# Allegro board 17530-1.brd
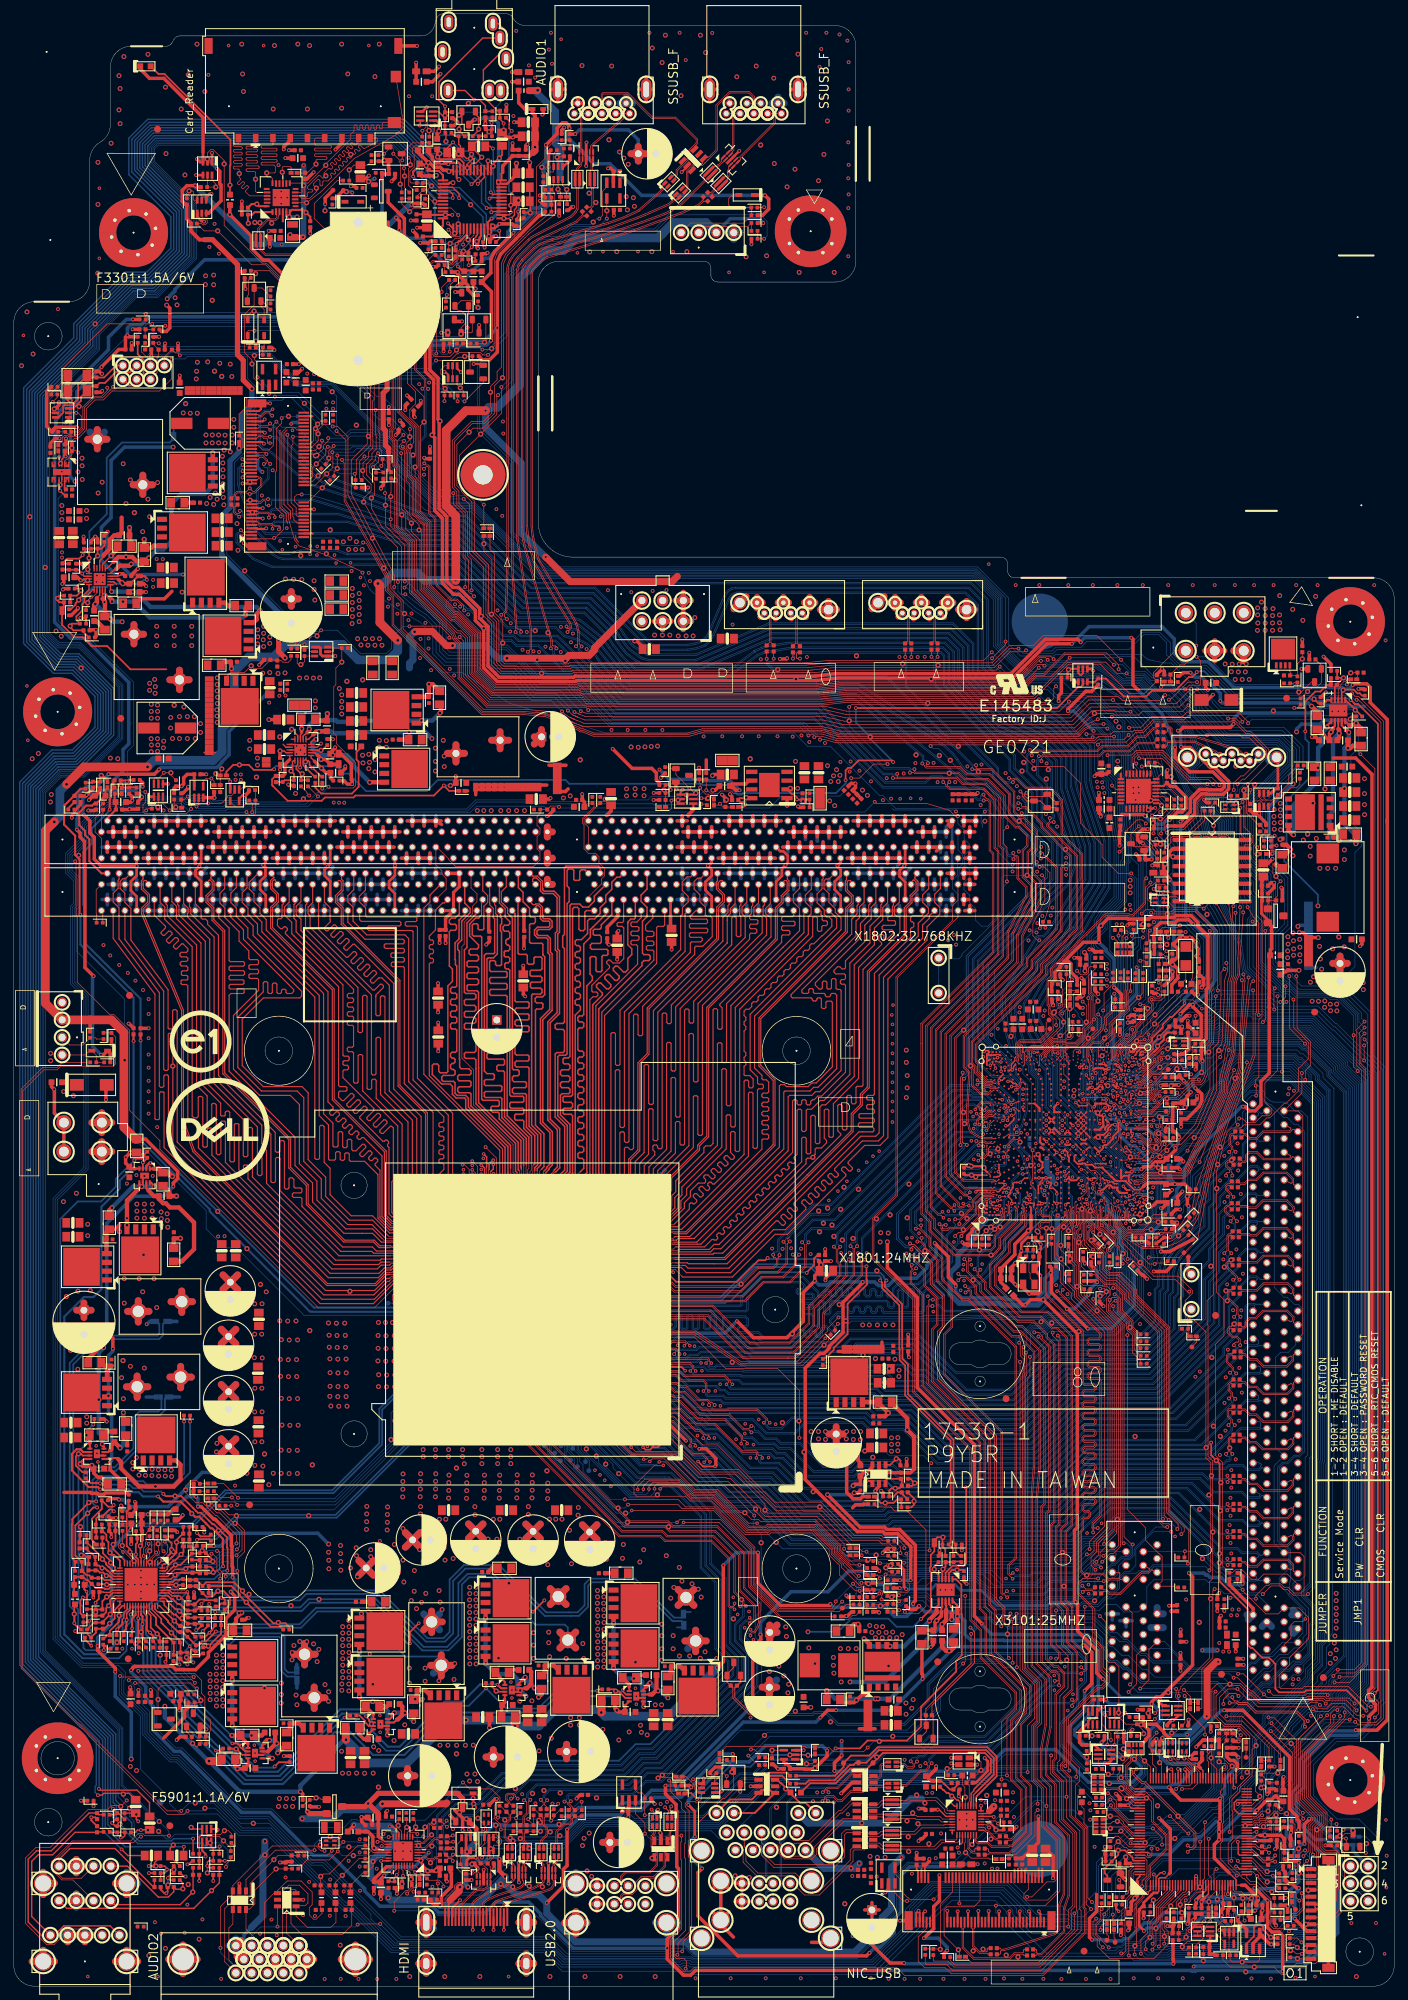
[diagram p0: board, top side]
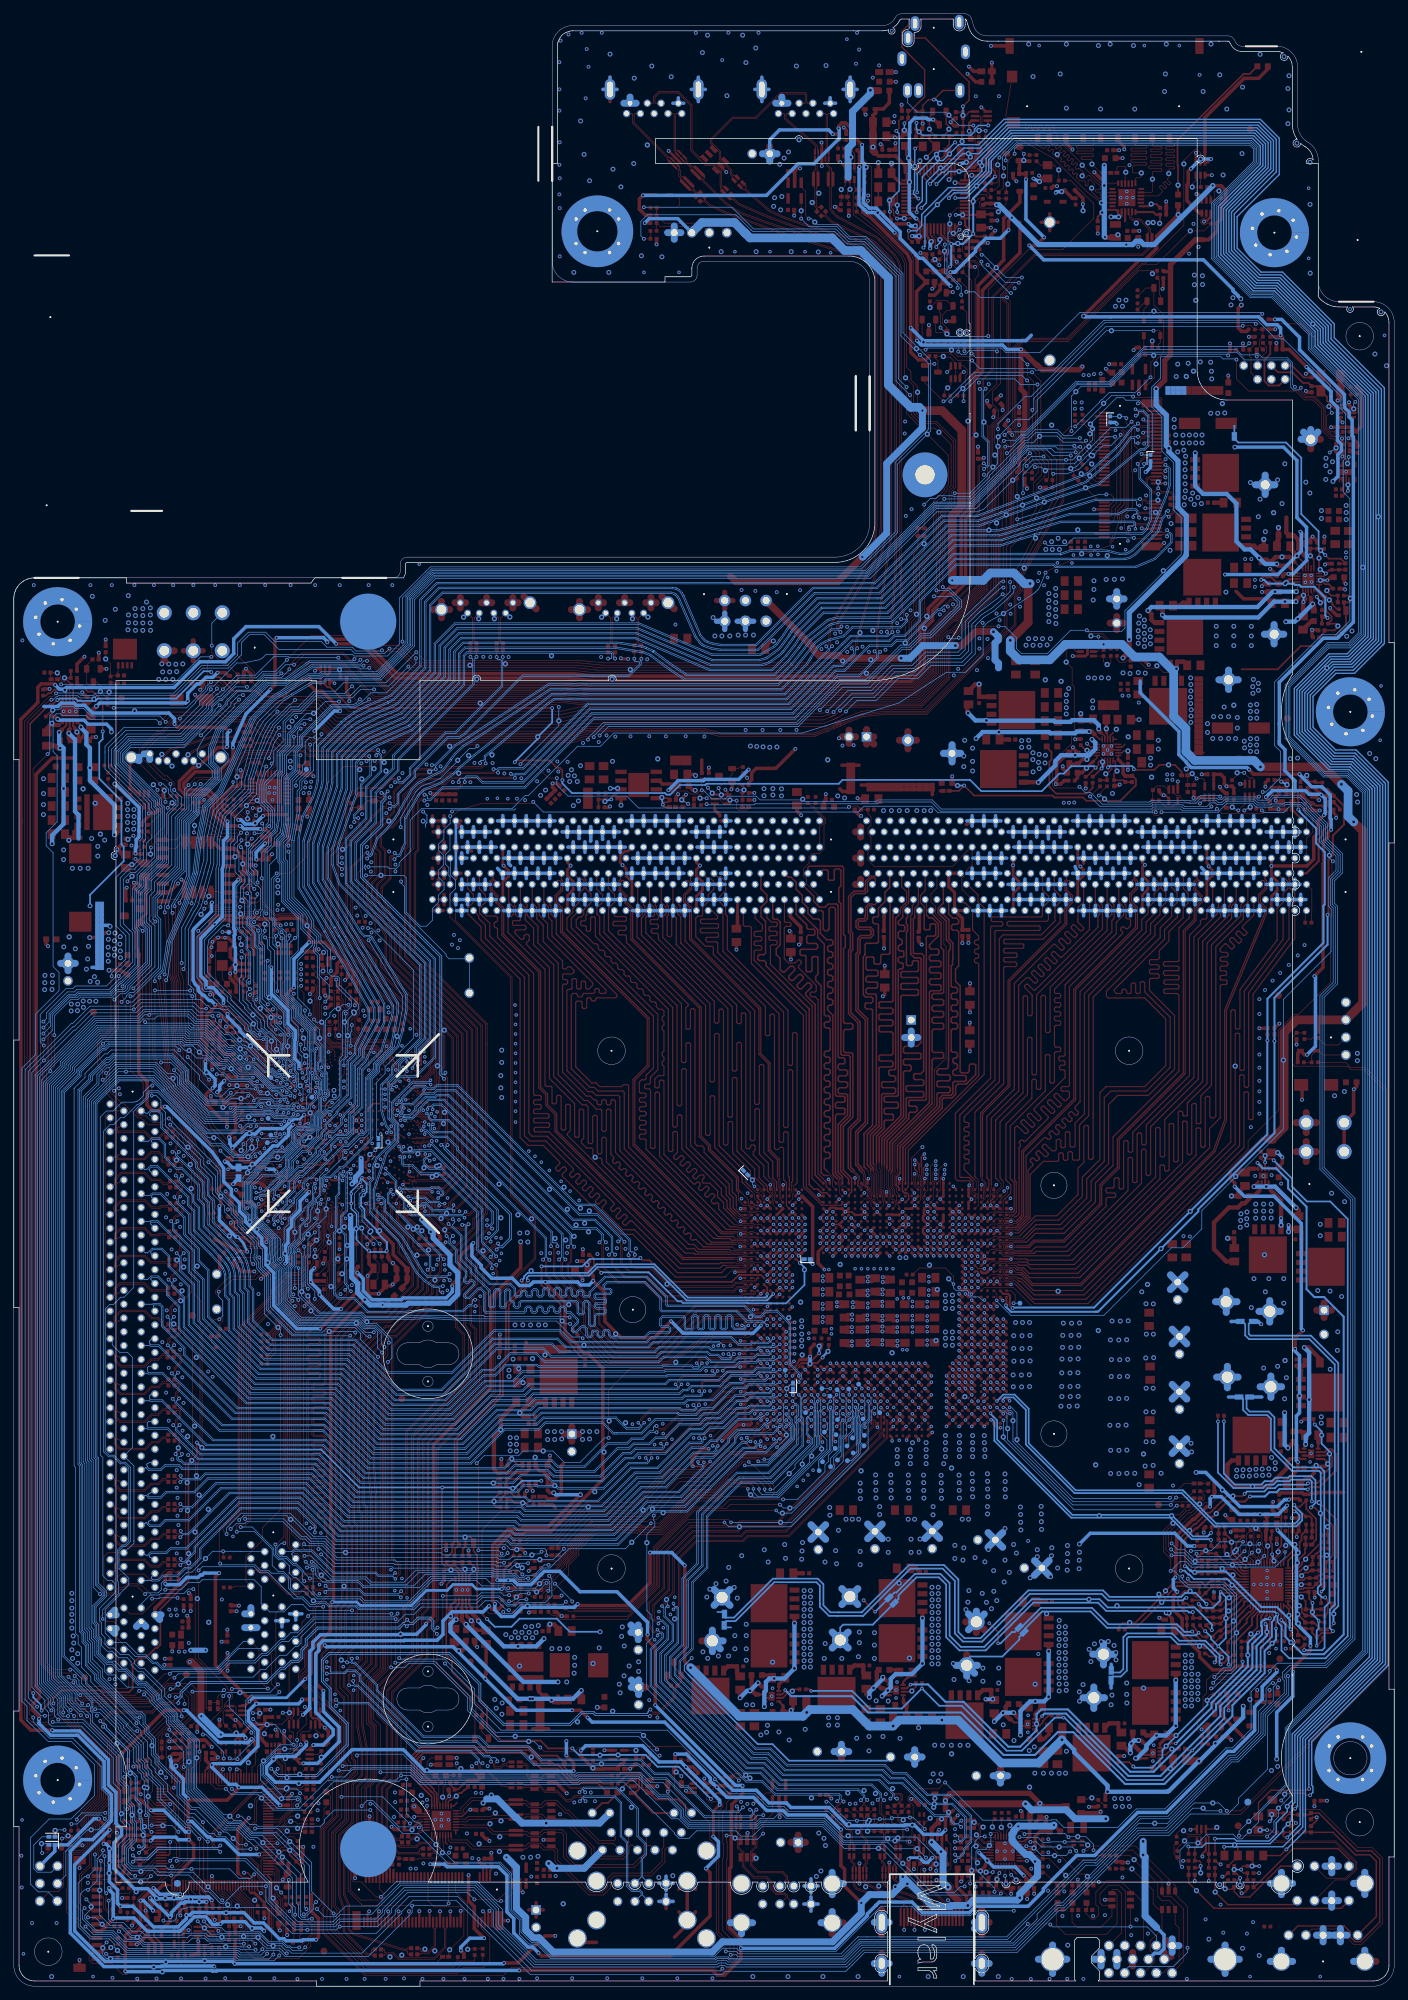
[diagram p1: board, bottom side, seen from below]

Outline 200 x 285.7 mm; copper layers: TOP, L2VCC, L3SGND, BOTTOM. Coordinates in mm from the lower left corner of the outline.
Outline path: 0,241 0,3 arc(0.88,0.88) 3,0 197,0 arc(199.12,0.88) 200,3 200,201 arc(199.12,203.12) 197,204 145,204 arc(144.29,204.29) 144,205 144,206 arc(143.71,206.71) 143,207 81,207 arc(77.46,208.46) 76,212 76,246.85 arc(76.88,248.97) 79,249.85 100,249.85 arc(100.71,249.56) 101,248.85 101,247.85 arc(101.29,247.14) 102,246.85 119,246.85 arc(121.12,247.73) 122,249.85 122,281 arc(121.12,283.12) 119,284 74.11,284 arc(73.12,284.26) 72.39,284.99 72.26,285.21 arc(71.89,285.57) 71.4,285.7 62.21,285.7 arc(61.61,285.51) 61.25,285 60.91,283.9 arc(60.18,282.89) 59,282.5 24.08,282.5 arc(23.58,282.37) 23.21,282 22.92,281.5 arc(22.56,281.13) 22.06,281 17,281 arc(14.88,280.12) 14,278 14,269.7 arc(13.6,268.2) 12.5,267.1 arc(11.4,266) 11,264.5 11,247 arc(10.12,244.88) 8,244 3,244 arc(0.88,243.12) 0,241 ; 3,239 arc(5,241) 7,239 arc(5,237) 3,239 ; 3,23.76 arc(5,25.76) 7,23.76 arc(5,21.76) 3,23.76 ; 3.94,33.02 arc(6.35,35.43) 8.76,33.02 arc(6.35,30.61) 3.94,33.02 ; 36.4,135.5 arc(38.4,137.5) 40.4,135.5 arc(38.4,133.5) 36.4,135.5 ; 36.4,60.5 arc(38.4,62.5) 40.4,60.5 arc(38.4,58.5) 36.4,60.5 ; 47.4,116 arc(49.3,117.9) 51.2,116 arc(49.3,114.1) 47.4,116 ; 47.4,80 arc(49.3,81.9) 51.2,80 arc(49.3,78.1) 47.4,80 ; 67.98,220.27 arc(69.33,218.92) 67.98,217.57 arc(66.63,218.92) 67.98,220.27 ; 108.42,98 arc(110.32,99.9) 112.22,98 arc(110.32,96.1) 108.42,98 ; 111.4,135.5 arc(113.4,137.5) 115.4,135.5 arc(113.4,133.5) 111.4,135.5 ; 111.4,60.5 arc(113.4,62.5) 115.4,60.5 arc(113.4,58.5) 111.4,60.5 ; 137.1,93.2 138.8,93.2 arc(140,93.6) 141.2,93.2 142.9,93.2 arc(144.5,91.6) 142.9,90 141.2,90 arc(140,89.6) 138.8,90 137.1,90 arc(135.5,91.6) 137.1,93.2 ; 137.1,43.2 138.8,43.2 arc(140,43.6) 141.2,43.2 142.9,43.2 arc(144.5,41.6) 142.9,40 141.2,40 arc(140,39.6) 138.8,40 137.1,40 arc(135.5,41.6) 137.1,43.2 ; 140,96.35 arc(140.75,95.6) 140,94.85 arc(139.25,95.6) 140,96.35 ; 140,88.35 arc(140.75,87.6) 140,86.85 arc(139.25,87.6) 140,88.35 ; 140,46.35 arc(140.75,45.6) 140,44.85 arc(139.25,45.6) 140,46.35 ; 140,38.35 arc(140.75,37.6) 140,36.85 arc(139.25,37.6) 140,38.35 ; 193,5 arc(195,7) 197,5 arc(195,3) 193,5

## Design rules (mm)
constraint set DEFAULT: min track width 0.127, pair gap 0.102
net group AUDIO_IO3_8_12: nets RP_MIC1_L RP_MIC1_R
net group CEC_STRAP: nets GPIO_LAN_RESET_N GPIO_PCI_RESET_N
net group DISPLAY_DDC: nets HDMI_CLK_CPU HDMI_DATA_CPU
net group H_PWRGD: nets H_PWRGD H_PWRGD_R
net group LAN_MDI0_DN: nets LAN_MDI0_DN LAN_MDI0_DN_C
net group LAN_MDI0_DP: nets LAN_MDI0_DP LAN_MDI0_DP_C
net group LAN_MDI1_DN: nets LAN_MDI1_DN LAN_MDI1_DN_C
net group LAN_MDI1_DP: nets LAN_MDI1_DP LAN_MDI1_DP_C
net group LAN_MDI2_DN: nets LAN_MDI2_DN LAN_MDI2_DN_C
net group LAN_MDI2_DP: nets LAN_MDI2_DP LAN_MDI2_DP_C
net group LAN_MDI3_DN: nets LAN_MDI3_DN LAN_MDI3_DN_C
net group LAN_MDI3_DP: nets LAN_MDI3_DP LAN_MDI3_DP_C
net group LED_4_5: nets SIO_GREEN SIO_YELLOW
net group PCH_LPSS_GSP: nets LPSS_GSPI0_MOSI LPSS_GSPI1_MOSI
net group PCH_RTCRST: nets PCH_RTCRST_PULLUP PCH_SRTCRSTB_PULLUP
net group PCIE_RX_CON_N5: nets PCIE_RX_CON_N5 PCIE_RX_PCH_N5
net group PCIE_RX_CON_P5: nets PCIE_RX_CON_P5 PCIE_RX_PCH_P5
net group PCIE_TX_CON_N5: nets PCIE_TX_CON_N5 PCIE_TX_PCH_N5
net group PCIE_TX_CON_N7: nets PCIE_TX_CON_N7 PCIE_TX_PCH_N7
net group PCIE_TX_CON_N8: nets PCIE_TX_CON_N8 PCIE_TX_PCH_N8
net group PCIE_TX_CON_P5: nets PCIE_TX_CON_P5 PCIE_TX_PCH_P5
net group PCIE_TX_CON_P7: nets PCIE_TX_CON_P7 PCIE_TX_PCH_P7
net group PCIE_TX_CON_P8: nets PCIE_TX_CON_P8 PCIE_TX_PCH_P8
net group PECI_CPU: nets PECI_CPU PECI_EC
net group PEG_TX_CON_N0: nets PEG_TX_CON_N0 PEG_TX_CPU_N0
net group PEG_TX_CON_N1: nets PEG_TX_CON_N1 PEG_TX_CPU_N1
net group PEG_TX_CON_N2: nets PEG_TX_CON_N2 PEG_TX_CPU_N2
net group PEG_TX_CON_N3: nets PEG_TX_CON_N3 PEG_TX_CPU_N3
net group PEG_TX_CON_N4: nets PEG_TX_CON_N4 PEG_TX_CPU_N4
net group PEG_TX_CON_N5: nets PEG_TX_CON_N5 PEG_TX_CPU_N5
net group PEG_TX_CON_N6: nets PEG_TX_CON_N6 PEG_TX_CPU_N6
net group PEG_TX_CON_N7: nets PEG_TX_CON_N7 PEG_TX_CPU_N7
net group PEG_TX_CON_N8: nets PEG_TX_CON_N8 PEG_TX_CPU_N8
net group PEG_TX_CON_N9: nets PEG_TX_CON_N9 PEG_TX_CPU_N9
net group PEG_TX_CON_N10: nets PEG_TX_CON_N10 PEG_TX_CPU_N10
net group PEG_TX_CON_N11: nets PEG_TX_CON_N11 PEG_TX_CPU_N11
net group PEG_TX_CON_N12: nets PEG_TX_CON_N12 PEG_TX_CPU_N12
net group PEG_TX_CON_N13: nets PEG_TX_CON_N13 PEG_TX_CPU_N13
net group PEG_TX_CON_N14: nets PEG_TX_CON_N14 PEG_TX_CPU_N14
net group PEG_TX_CON_N15: nets PEG_TX_CON_N15 PEG_TX_CPU_N15
net group PEG_TX_CON_P0: nets PEG_TX_CON_P0 PEG_TX_CPU_P0
net group PEG_TX_CON_P1: nets PEG_TX_CON_P1 PEG_TX_CPU_P1
net group PEG_TX_CON_P2: nets PEG_TX_CON_P2 PEG_TX_CPU_P2
net group PEG_TX_CON_P3: nets PEG_TX_CON_P3 PEG_TX_CPU_P3
net group PEG_TX_CON_P4: nets PEG_TX_CON_P4 PEG_TX_CPU_P4
net group PEG_TX_CON_P5: nets PEG_TX_CON_P5 PEG_TX_CPU_P5
net group PEG_TX_CON_P6: nets PEG_TX_CON_P6 PEG_TX_CPU_P6
net group PEG_TX_CON_P7: nets PEG_TX_CON_P7 PEG_TX_CPU_P7
net group PEG_TX_CON_P8: nets PEG_TX_CON_P8 PEG_TX_CPU_P8
net group PEG_TX_CON_P9: nets PEG_TX_CON_P9 PEG_TX_CPU_P9
net group PEG_TX_CON_P10: nets PEG_TX_CON_P10 PEG_TX_CPU_P10
net group PEG_TX_CON_P11: nets PEG_TX_CON_P11 PEG_TX_CPU_P11
net group PEG_TX_CON_P12: nets PEG_TX_CON_P12 PEG_TX_CPU_P12
net group PEG_TX_CON_P13: nets PEG_TX_CON_P13 PEG_TX_CPU_P13
net group PEG_TX_CON_P14: nets PEG_TX_CON_P14 PEG_TX_CPU_P14
net group PEG_TX_CON_P15: nets PEG_TX_CON_P15 PEG_TX_CPU_P15
net group PM_DOWN_CPU: nets PM_DOWN_CPU PM_DOWN_PCH
net group PM_SYNC_CPU: nets PM_SYNC_CPU PM_SYNC_PCH
net group POWER_12_5: nets U1.6 U1.24
net group POWER_40_5: nets 1D8V_SB_CNVI 5V_AUD_S5
net group POWER_80_5: nets 1V_VCCA_XTAL 1V_VCCDSW
net group PROC_TRIGIN_CPU: nets PROC_TRIGIN_CPU PROC_TRIGIN_PCH
net group PROC_TRIGOUT_CPU: nets PROC_TRIGOUT_CPU PROC_TRIGOUT_PCH
net group PWM_12_12: nets DLDO_CAP LDO5V
net group SATA_RX_CON_N0: nets SATA_RX_CON_N0 SATA_RX_PCH_N0
net group SATA_RX_CON_N3: nets SATA_RX_CON_N3 SATA_RX_PCH_N3
net group SATA_RX_CON_P0: nets SATA_RX_CON_P0 SATA_RX_PCH_P0
net group SATA_RX_CON_P3: nets SATA_RX_CON_P3 SATA_RX_PCH_P3
net group SATA_RX_PCH_N1: nets SATA_RX_PCH_N1 SATA_RX_PCH_N1_C
net group SATA_RX_PCH_P1: nets SATA_RX_PCH_P1 SATA_RX_PCH_P1_C
net group SATA_TX_CON_N0: nets SATA_TX_CON_N0 SATA_TX_PCH_N0
net group SATA_TX_CON_N2: nets SATA_TX_CON_N2 SATA_TX_PCH_N2
net group SATA_TX_CON_N3: nets SATA_TX_CON_N3 SATA_TX_PCH_N3
net group SATA_TX_CON_P0: nets SATA_TX_CON_P0 SATA_TX_PCH_P0
net group SATA_TX_CON_P2: nets SATA_TX_CON_P2 SATA_TX_PCH_P2
net group SATA_TX_CON_P3: nets SATA_TX_CON_P3 SATA_TX_PCH_P3
net group SATA_TX_PCH_N1: nets SATA_TX_PCH_N1 SATA_TX_PCH_N1_C
net group SATA_TX_PCH_P1: nets SATA_TX_PCH_P1 SATA_TX_PCH_P1_C
net group SD_CLK_BD: nets SD_CLK_BD U1.15
net group THERMTRIP#_CPU: nets THERMTRIP#_CPU THERMTRIP#_PCH
net group TRACE_10_10: nets AUD_VREF PWRGD_PS
net group USB30_TX_CMC_N1: nets USB30_TX_CMC_N1 USB30_TX_PCH_N1
net group USB30_TX_CMC_N2: nets USB30_TX_CMC_N2 USB30_TX_PCH_N2
net group USB30_TX_CMC_P1: nets USB30_TX_CMC_P1 USB30_TX_PCH_P1
net group USB30_TX_CMC_P2: nets USB30_TX_CMC_P2 USB30_TX_PCH_P2
net group USB_CON_PN1: nets USB_CON_PN1 USB_PCH_PN1
net group USB_CON_PN2: nets USB_CON_PN2 USB_PCH_PN2
net group USB_CON_PN5: nets USB_CON_PN5 USB_PCH_PN5
net group USB_CON_PN6: nets USB_CON_PN6 USB_PCH_PN6
net group USB_CON_PN7: nets USB_CON_PN7 USB_PCH_PN7
net group USB_CON_PN8: nets USB_CON_PN8 USB_PCH_PN8
net group USB_CON_PN9: nets USB_CON_PN9 USB_PCH_PN9
net group USB_CON_PP1: nets USB_CON_PP1 USB_PCH_PP1
net group USB_CON_PP2: nets USB_CON_PP2 USB_PCH_PP2
net group USB_CON_PP5: nets USB_CON_PP5 USB_PCH_PP5
net group USB_CON_PP6: nets USB_CON_PP6 USB_PCH_PP6
net group USB_CON_PP7: nets USB_CON_PP7 USB_PCH_PP7
net group USB_CON_PP8: nets USB_CON_PP8 USB_PCH_PP8
net group USB_CON_PP9: nets USB_CON_PP9 USB_PCH_PP9
net group AUDIO_HDA_4_5: nets AUD_LINK_SDO_C AUD_LINK_SDO_R1 HDA_BITCLK_CODEC HDA_BITCLK_PCH HDA_RST#_CODEC HDA_RST#_PCH HDA_SDIN0_CODEC HDA_SDIN0_PCH HDA_SDOUT_CODEC HDA_SDOUT_PCH HDA_SYNC_CODEC HDA_SYNC_PCH
net group AUDIO_IO1_8_6: nets AUD_BEEP AUD_LINE2_L AUD_LINE2_R AUD_MIC1_L AUD_MIC2_L AUD_MIC2_L_C AUD_MIC2_R AUDOUT_L AUDOUT_LL AUDOUT_RR HP_OUT_L HP_OUT_R LINE1_LL LINE1_LL_C LINE1_RR LINE1_RR_C LINEIN_L LINEIN_R MIC1_LL_C MIC1_RR_C PF_MIC2_LL RP_AUDOUT_L RP_AUDOUT_R RP_LINE1_L RP_LINE1_R
net group AUDIO_IO2_8_8: nets AUD_MIC1_R FP_MIC2_L FP_OUT_L FP_OUT_LL FP_OUT_R FP_OUT_RR
net group AUDIO_IO4_8_7: nets AUD_LINE1_L AUD_LINE1_R AUDOUT_R MIC1_LL MIC1_RR
net group AUDIO_JD: nets FRONT_JD LINE1_JD LINE1_JD/LINE2_JD LINE2_JD MIC1_JD MIC1_JD/FRONT_JD
net group AUDIO_OTHER: nets AUD_AZACPU_SCLK AUD_AZACPU_SCLK_R AUD_AZACPU_SDI AUD_AZACPU_SDI_R AUD_AZACPU_SDO AUD_AZACPU_SDO_R AUD_BEEP_R
net group AUDIO_VREFO_20_10: nets LINE2_VREFO MIC1_VREFO_LL MIC1_VREFO_RR MIC2_VREFO
net group CEC_PLTRST_N: nets PLTRST#_PCH PLTRST#_SIO PLTRST_BUF_LAN_N PLTRST_BUF_PCI_N
net group CEC_PS_ON: nets PCH_PS_ON_N
net group CNVI_BUS: nets PCM_OUT PCM_OUT_C PCM_OUT_PCH PCM_SYNC PCM_SYNC_C PCM_SYNC_PCH Q9103 W_DISABLE#1 W_DISABLE#2
net group COM: nets SP_CTS_N SP_DCD_N SP_DSR_N SP_DTR_N SP_RI_N SP_RTS_N SP_RXD_N SP_RXD_N_CON SP_TXD_N SP_TXD_N_1 SP_TXD_SIO SP_TXD_SIO_CON
net group CPU_CFG_RCOMP: nets TPEV_CFG_RCOMP
net group DDI_HDP: nets DP_HPD_CPU HDMI_DET_CPU VGA1_DETECT
net group DDR_VREF_CA: nets DIMM_CA_CPU_VREF_RC DIMM_CA_VREF_A DIMM_CA_VREF_A_L DIMM_CA_VREF_B DIMM_CA_VREF_B_L DIMM_DQ_CPU_VREF_B_RC M_VREF_DQ_DIM1 V_SM_VREF_CNT
net group DEEPSLEEP_CON_4_5: nets FP_RST_N_CN PCH_DPWROK PCH_SLP_A_N PWRBTN_N_CN SIO_PS_ON_N SLP_A_N_CN SLP_S0_N SLP_S4_N_SFR SLP_S4_N_SFR_1 SLP_S4_N_SFR_2 SLP_S4_N_SFR_G SLP_SUSB SUS_WARNB VTT_EN
net group DSW_4_8: nets SUS_ACK_EN_N SUS_PWR_ACK SUS_WARNB_R
net group FAN_CPU: nets CPU_FAN_CTRL_CONN CPU_FAN_CTRL_SIO CPU_FAN_TACH_1 CPU_FAN_TACH_SIO SYS_FAN_CTRL_CONN SYS_FAN_CTRL_SIO SYS_FAN_TACH_1
net group FAN_SYS1: nets SYS_FAN_TACH_SIO
net group FDI_COMP: nets FDI_COMP
net group GPIO_4: nets 3P3V_S5_EN ACPRESENT BATLOW_N CHASSIS_ID_0 CNV_BRI_DT CNV_BRI_DT_R CNV_BRI_RSP CNV_BRI_RSP_R CNV_DET_S CNV_RGI_DT CNV_RGI_DT_R CNV_RGI_RSP CNV_RGI_RSP_R CNV_WT_RCOMP DDR_VTT_CNTL_CPU DDR_VTT_CNTL_GATE DDR_VTT_CNTL_R DDSP_B_TX_N0 DEVSLP DEVSLP_N DIMM1_EVENT_N DIMM2_EVENT_N EAPD FORM_FAC_ID_0 FORM_FAC_ID_1 FORM_FAC_ID_2 FP_CBL_DET FP_CBL_DET_PD GPP_A8 GPP_H_12 GPP_H_15 GPP_K3 H_SKTOCC_CPU H_SKTOCC_N HDMI1_DETECT HDMI_DET_CON LANCLK_REQ_U_N LPC_PME_N ME_CNTL ME_CNTL_1 ME_CNTL_2 MUTE MUTE_AUDOUT_LL MUTE_AUDOUT_RR MUTE_FP_OUT_LL MUTE_FP_OUTR_RR PC_SPKR_DET_PD PCH_HEATSINK_DET PW_CLEAR Q82_B Q83_B Q84_B Q84_E Q84_E2 Q85_B S0_5V_EN S4_VPP_OR SB3V_EN SD_RCOMP SLP_S4_VPP_N SM_PGCNTL SMBALERT_N SML0ALERT# SSD_PEDET SSD_PEWAKE_N SUS_PWR_ACK_5V_DUAL SUS_PWR_ACK_5V_DUAL_L SUS_PWR_ACK_BJT SUS_PWR_ACK_BJT_L SUS_PWR_ACK_R TMIN_SHIFT TMIN_SHIFT_PCH UART_BT_WAKE_N USB2_ID USB2_VBUSSENSE V5_ALW_MON V5_ALW_MON_1 V5_ALW_MON_2 VDDQ_EN VGA_CABLE_DET_N VPP_EN VPP_EN_DDR4 WAKE_M2_SSD_N WLAN_PEDET WLAN_USB_DET
net group GPIO_4_5: nets GPP_A7 GPP_K5 I2S1_SFRM
net group HDD_LED_CTL: nets DAS/DSS# DAS/DSS#_NMOS PCH_SATA_LED_N PCH_SATA_LED_NMOS
net group HDMI_DATA_CMC_N0: nets HDMI_DATA_CMC_N0 HDMI_DATA_CON_N0 HDMI_DATA_CPU_N0
net group HDMI_DATA_CMC_N1: nets HDMI_DATA_CMC_N1 HDMI_DATA_CON_N1 HDMI_DATA_CPU_N1
net group HDMI_DATA_CMC_N2: nets HDMI_DATA_CMC_N2 HDMI_DATA_CON_N2 HDMI_DATA_CPU_N2
net group HDMI_DATA_CMC_N3: nets HDMI_DATA_CMC_N3 HDMI_DATA_CON_N3 HDMI_DATA_CPU_N3
net group HDMI_DATA_CMC_P0: nets HDMI_DATA_CMC_P0 HDMI_DATA_CON_P0 HDMI_DATA_CPU_P0
net group HDMI_DATA_CMC_P1: nets HDMI_DATA_CMC_P1 HDMI_DATA_CON_P1 HDMI_DATA_CPU_P1
net group HDMI_DATA_CMC_P2: nets HDMI_DATA_CMC_P2 HDMI_DATA_CON_P2 HDMI_DATA_CPU_P2
net group HDMI_DATA_CMC_P3: nets HDMI_DATA_CMC_P3 HDMI_DATA_CON_P3 HDMI_DATA_CPU_P3
net group KBMS: nets KBRST_N KCLK KDAT MCLK MDAT
net group LAN_8111H: nets RTL_ISOLATE_N
net group LAN_LED: nets LAN_LEDACT_R# LINK_ACTIVITY_N SPEED_100*_CON SPEED_100_N SPEED_1000*_CON SPEED_1000_N
net group LAN_WG1217LM: nets LANWAKE_R_N
net group LPC: nets LPC_AD_PCH_P0 LPC_AD_PCH_P1 LPC_AD_PCH_P2 LPC_AD_PCH_P3 LPC_FRAME#_PCH LPC_FRAME#_PCH_R LPC_SERIRQ_PCH
net group LPC_CLK: nets LPC_CLK_14M_DEBUG LPC_CLK_14M_EC LPC_CLK_33M_EC LPC_CLK_PCH_P0 LPC_CLK_PCH_P1
net group OSCILLATION: nets LAN_XTALI LAN_XTALO LAN_XTALO_C PCH_RTCRST_DOWN XCLK_RBIAS
net group OSCILLATION_38D4: nets PULSAR_38D4M_REFCLK
net group PCH_CIRTIAL: nets VR_READY VR_READY_A VR_READY_B VR_READY_IMVP XDP_VR_READY
net group PCH_CIRTIAL2: nets FP_RST_N PCH_SIO_DPWROK PCH_SYSPWROK PCH_WAKE_N PWR_BTNJ_C PWRBTN_N RSMRST_SIO_N RSMRST_SIO_N_1
net group PCI: nets PCIAUX_GATE
net group PECI: nets PCH_PECI PECI_READY SIO_PECI_REQ_N
net group PEG_CLKREQ_PCH: nets PEG_CLKREQ1_PCH# PEG_CLKREQ2_PCH# PEG_CLKREQ3_PCH# PEG_CLKREQ8_PCH# PEG_CLKREQ9_PCH#
net group PEG_RCOMP: nets PCIE_RCOMP_N PCIE_RCOMP_P PEG_RCOMP_CPU
net group POWER_10_5: nets HD_LED_PWR1 HDD_LED_PWR1 LAN_RSET PWR_LED_G PWR_LED_Y VCCPLL_OC_R
net group POWER_20_5: nets ALDO_CAP CBN CBP CPVEE EDP_AVC33 EDP_DAC33
net group POWER_35_5: nets 3D3V_AUD_S0 3D3V_SPI 3P0V_BAT_VREG
net group POWER_100_5: nets 5V_HDMI_CONN
net group PROCHOT#_CPU: nets PROCHOT#_CPU PROCHOT#_CPU_R PROCHOT#_EC PROCHOT#_IMVP
net group PWM_8_5: nets DCPRTC
net group PWM_10_10: nets SB3V_CT2 SB5V_CT1 VCCIO_SENSE
net group PWM_20_10: nets CAP_1 TRST_N VIN_DET
net group PWM_LED_20: nets SATA_LED_OUT
net group PWR_10_10: nets PWR_1D0V_CS PWR_1D0V_FB PWR_1D0V_PG PWR_1D0V_RF PWR_2D5V_EN PWR_2D5V_FB PWR_3V_CS2 PWR_3V_EN2 PWR_3V_FB2 PWR_3V_FB2_A PWR_5V_CS1 PWR_5V_EN1 PWR_5V_FB1 PWR_5V_FB1_A PWR_DDR4_CS PWR_DDR4_FB PWR_GT_COMP PWR_GT_COMP_A PWR_GT_COMP_R PWR_GT_CSCOMP PWR_GT_CSP1_IC PWR_GT_CSP2_IC PWR_GT_CSREF PWR_GT_CSSUM PWR_GT_DOUT PWR_GT_EN1 PWR_GT_EN2 PWR_GT_FB PWR_GT_ILIM PWR_GT_IOUT PWR_GT_TCP PWR_GT_TSNS PWR_GT_TSNS_R PWR_GT_VSN PWR_GT_VSP PWR_PSYS PWR_RT6575_PG PWR_VCCIO_FB PWR_VCCIO_FB1 PWR_VCCIO_FB2 PWR_VCCIO_FB3 PWR_VCCIO_SS PWR_VCCIO_VCCSA_EN PWR_VCCSA_CS PWR_VCCSA_FB PWR_VCCSA_FB1 PWR_VCCSA_PG PWR_VCCSA_RF PWR_VCORE_COMP PWR_VCORE_COMP_A PWR_VCORE_COMP_R PWR_VCORE_CSCOMP PWR_VCORE_CSP1_IC PWR_VCORE_CSP2_IC PWR_VCORE_CSP3_IC PWR_VCORE_CSP4_IC PWR_VCORE_CSREF PWR_VCORE_CSSUM PWR_VCORE_DOUT PWR_VCORE_DRVON PWR_VCORE_EN1 PWR_VCORE_EN2 PWR_VCORE_EN3 PWR_VCORE_EN4 PWR_VCORE_FB PWR_VCORE_ILIM PWR_VCORE_IOUT PWR_VCORE_SCLK PWR_VCORE_SDIO PWR_VCORE_TCP PWR_VCORE_TSNS PWR_VCORE_TSNS_R PWR_VCORE_VRMP PWR_VCORE_VSN PWR_VCORE_VSP PWR_VDDQ_PG PWR_VDDQ_PG_ISOLATE PWR_VDDQ_S3_EN PWR_VDDQ_S5_EN PWR_VDDQ_TON
net group PWR_12_12: nets PWR_GT_PWM1 PWR_GT_PWM2 PWR_VCORE_PWM1 PWR_VCORE_PWM2 PWR_VCORE_PWM3 PWR_VCORE_PWM4
net group PWR_20_10: nets PWR_1D0V_VCC PWR_GT_VCC1 PWR_GT_VCC2 PWR_VCCIO_VCC PWR_VCCSA_VCC PWR_VCORE_VCC PWR_VCORE_VCC1 PWR_VCORE_VCC2 PWR_VCORE_VCC3 PWR_VCORE_VCC4 PWR_VDDQ_VDDP PWR_VDDQ_VIOP
net group PWR_25_20: nets PWR_1D0V_BOOT PWR_1D0V_BOOT_R PWR_1D0V_LGATE PWR_1D0V_SNB PWR_1D0V_UGATE PWR_1D0V_UGATE_R PWR_3D3V_SN PWR_3V_BOOT2 PWR_3V_BOOT2_R PWR_3V_LGATE2 PWR_3V_UGATE2 PWR_3V_UGATE2R PWR_5V_BOOT1 PWR_5V_BOOT1_R PWR_5V_LGATE1 PWR_5V_SN PWR_5V_UGATE1 PWR_5V_UGATE1R PWR_DDR4_BT PWR_DDR4_BT1 PWR_DDR4_LG PWR_DDR4_UG PWR_DDR4_UG1 PWR_GT_BST1 PWR_GT_BST1_R PWR_GT_BST2 PWR_GT_BST2_R PWR_GT_HG1 PWR_GT_HG1_R PWR_GT_HG2 PWR_GT_HG2_R PWR_GT_LG1 PWR_GT_LG2 PWR_GT_SNB1 PWR_GT_SNB2 PWR_VCCIO_DRV PWR_VCCIO_DRV_R PWR_VCCSA_BOOT PWR_VCCSA_BOOT_R PWR_VCCSA_LG PWR_VCCSA_SNB PWR_VCCSA_UG PWR_VCCSA_UG_R PWR_VCORE_BST1 PWR_VCORE_BST1_R PWR_VCORE_BST2 PWR_VCORE_BST2_R PWR_VCORE_BST3 PWR_VCORE_BST3_R PWR_VCORE_BST4 PWR_VCORE_BST4_R PWR_VCORE_HG1 PWR_VCORE_HG1_R PWR_VCORE_HG2 PWR_VCORE_HG2_R PWR_VCORE_HG3 PWR_VCORE_HG3_R PWR_VCORE_HG4 PWR_VCORE_HG4_R PWR_VCORE_LG1 PWR_VCORE_LG2 PWR_VCORE_LG3 PWR_VCORE_LG4 PWR_VCORE_SNB1 PWR_VCORE_SNB2 PWR_VCORE_SNB3 PWR_VCORE_SNB4 PWR_VDDQ_SNB
net group PWR_40_10: nets PWR_5V3D3V_LDO3 PWR_DDR4_VDDQ PWR_DDR4_VTTREF PWR_RT6575_LDO5
net group PWRGD&RST_4_8: nets 5V_DISPLAY_SFR_G 12V_CPU_N 12VBDC_EN_2 12VBDC_EN_3 12VCPU_EN_2 ALL_SYS_PWRGD EC_PWRGD_3V GPIO_PEG_RESET_N GPP_J1 H_RSTOUT_XDP_N H_TRST_N_R ITP_PMODE NGFF_WIFI_PWR_CRL NGFF_WIFI_PWR_EN PCH_PWROK PCH_PWROK_EC PCIE_SLOT1_PRSNT_N PCIE_SLOT2_PRSNT_N PCIRST1# PCIRST2# PLTRST_LAN_N PLTRST_PCI_N PLTRST_PEG_N PSPWRGD PWRGD_VPP S3_QUK S4_VPP_OR_R SIO_SPKR SLP_S0_PLT_N SLP_S3_N SLP_S3_N_CN SLP_S3_N_Q4205 SLP_S3_N_Q4207 SLP_S4_N SLP_S4_N_CN SLP_S5_N SLP_WLAN_N SM_DRAMRST# V_VCC3P3_EN V_VCC3P3_EN_R VCCST_GD_CPU VCCST_GD_DRIVER VCTRL_VCC_EN VDDQ_EN_CR VPP_EN_CR VR_ENABLE VR_ENABLE_IMVP XDP_PWRGD
net group RGB_4_20: nets BLUE_CRT EDP_5VDDCCL EDP_5VDDCDA EDP_BLUE_P EDP_GREEN_P EDP_HSYNC EDP_HSYNC_C EDP_RED_P EDP_VSYNC EDP_VSYNC_C GREEN_CRT RED_CRT
net group SATA_RX_CON_N2: nets SATA_RX_PCH_N2
net group SATA_RX_CON_P2: nets SATA_RX_PCH_P2
net group SIO_PWR_SNCE: nets MB_REG_PG MB_REG_PG_1 MB_REG_PG_2 MB_REG_PG_3 MEM_REG_PG MEM_REG_PG_1 MEM_REG_PG_2 PWR2_PRSN_1 PWR2_PRSN_2 PWR2_PRSNT
net group SIO_SCH5553: nets A20GATE PCIVAUX_CTRL PS_ON_N
net group SMBUS: nets DDPC_CTRL_CLK DDPC_CTRL_DATA DDPD_CTRL_CLK DDPD_CTRL_DATA HDMI_CLK_CON HDMI_DATA_CON I2C0_SCL_VGA I2C0_SDA_VGA SIO_SMBCLK1 SIO_SMBCLK2 SIO_SMBDAT1 SIO_SMBDAT2 SMB_CLK_MAIN SMB_CLK_RESUME SMB_DATA_MAIN SMB_DATA_RESUME SML0CLK_PCH SML0DATA_PCH SMLICLK_PCH SMLIDATA_PCH
net group SPEKER_4_6: nets SPKR
net group SPI: nets SPI_CS_PCH_N0 SPI_CS_PCH_N2 SPI_SI_TPM SPI_SO_PCH SPI_SO_PCH_TPM SPI_SO_ROM1 SPI_SO_TPM SPI_WP_PCH SPI_WP_ROM1
net group SPI_CLK: nets SPI_CLK_TPM
net group SPI_CLK_PCH: nets SPI_CLK_PCH
net group SPI_HOLD_PCH: nets SPI_HOLD_PCH
net group SPI_SI_PCH: nets SPI_SI_PCH
net group SUS_CLOCK: nets SUSCLK SUSCLK_SIO SUSCLK_WIFI
net group TH_SET: nets TH_SET
net group TP_4_5: nets BC1_TP CATERR#_CPU CPU1_AY3 CPU1_G8 DISP_UTIL_CPU GPD7 M_VREF_DQ_DIM0 SKL_CNL_N TP_CLKIN_XTAL TP_CPU1_L8 TP_DIMM1_PIN1 TP_DIMM1_PIN145 TP_DIMM2_PIN1 TP_DIMM2_PIN145 TP_SLP_LAN_N TP_VCCPHY_SENSE TP_VSS_AL37 TP_VSSPHY_SENSE TPM_PP UART0_RX UART0_TX
net group TPM: nets PIRQA_N TPM_CS TPM_PIRQ TPM_RST_R
net group TRACE_4_5: nets +12V_PG_U29 EDP_EXPCLKIN EDP_GPI1 EDP_GPI2 EDP_GPI3 EDP_LDORSTB POL1_SDA POL2_SCL SIO_GREEN_1 SIO_YELLOW_1 SYS_FAN2_TACH_SIO TS_CRIT#
net group USB30_RX_CON_N1: nets USB30_RX_PCH_N1
net group USB30_RX_CON_N2: nets USB30_RX_PCH_N2
net group USB30_RX_CON_P1: nets USB30_RX_PCH_P1
net group USB30_RX_CON_P2: nets USB30_RX_PCH_P2
net group USB_OC: nets USB_OC0_R_N USB_OC1_R_N USB_OC2_R_N USB_OC3_R_N USB_OC4_R_N USB_OC5_R_N USB_OC6_R_N
net group VBAT_RST_4_10: nets PCH_INTRUDER_N PCH_RTCRST_N RTCRST_N_CN
net group VRD_4_10: nets VIDALERT#_CPU VIDALERT#_CPU_R VIDSCK_CPU VIDSCK_CPU_R VIDSOUT_CPU VIDSOUT_CPU_R
net group XDP: nets H_PRDY_N H_PREQ_N H_TCK H_TDI H_TDO H_TMS H_TRST_N PCH_JTAG_TCK_48077565 PCH_JTAG_TDI PCH_JTAG_TDO PCH_JTAG_TMS PCH_XDP_PRDY_R_N PCH_XDP_PREQ_R_N SKL_PCUDEBUG_0 SKL_PCUDEBUG_1 SKL_PCUDEBUG_2 SKL_PCUDEBUG_3 SKL_PCUDEBUG_4 SKL_PCUDEBUG_5 SKL_PCUDEBUG_6 SKL_PCUDEBUG_7 SKL_PCUDEBUG_8 SKL_PCUDEBUG_9 SKL_PCUDEBUG_10 SKL_PCUDEBUG_11 SKL_PCUDEBUG_12 SKL_PCUDEBUG_13 SKL_PCUDEBUG_14 SKL_PCUDEBUG_15 XDP_PCUDEBUG_3 XDP_PWR_DEBUG
net group XIO2001: nets PCH_PME_N

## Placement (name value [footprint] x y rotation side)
ATX1  BAOT-CONN6B-S-GP  [W4202VT-203P-D]  174 193.9 0 top
ATX2  FOX-CONN4F-1-GP  [HM3502E-P1]  10 122.99 90 top
AUD1  AUDIO-JK187-GP  [ABA-JAK-028-K03]  10.3 3.59 180 top
BT2501  BAT-20-00950-1A01-A-GP-U  [20-00950-1A01-A-U]  49.91 243.71 90 top
C402  SCD1U16V2KX-L-GP  [C402H22]  124.08 54.23 90 top
C403  SCD1U16V2KX-L-GP  [C402H22]  127.13 63.37 270 top
C601  SCD1U16V2KX-3DLGP  [C402H22]  17.35 138.33 180 top
C602  SCD022U16V2KX-3DLGP  [C402H22]  8.79 171.96 0 top
C603  SCD1U16V2KX-3DLGP  [C402H22]  18.36 138.3 180 top
C801  SC1U10V2KX-1DLGP  [C402H22]  117.09 105.92 90 top
C802  SCD1U25V2KX-1-DL-GP  [C402H22]  183.34 157.28 90 top
C803  SCD1U16V2KX-L-GP  [C402H22]  181.31 157.28 270 top
C804  SC10U25V5KX-DL-GP  [C805H58]  181.03 161.7 180 top
C805  SCD1U16V2KX-3DLGP  [C402H22]  181.28 159.41 90 top
C806  SCD1U16V2KX-L-GP  [C402H22]  179.13 170.8 0 top
C807  SCD1U16V2KX-3DLGP  [C402H22]  127.43 92.32 0 top
C808  SCD1U16V2KX-3DLGP  [C402H22]  129.59 92.39 0 top
C1025  SC22U6D3V5MX-L3-GP  [C805H58]  75.69 171.96 90 top
C1026  SC22U6D3V5MX-L3-GP  [C805H58]  86.53 172.01 0 top
C1027  SC22U6D3V5MX-L3-GP  [C805H58]  87.42 150.78 0 top
C1028  SC47U6D3V5MX-1DL-GP  [C805H54]  61.49 137.49 180 top
C1029  SC47U6D3V5MX-1DL-GP  [C805H54]  73.81 145.62 180 top
C1030  SC47U6D3V5MX-1DL-GP  [C805H54]  95.31 152.22 0 top
C1031  SC47U6D3V5MX-1DL-GP  [C805H54]  61.47 143.13 180 top
C1032  SC22U6D3V5MX-2DLGP  [C805H54]  117.73 103.63 90 top
C1033  SC1U10V2KX-1DLGP  [C402H22]  117.09 105.03 90 top
C1101  SCD1U16V2KX-3DLGP  [C402H22]  68.91 152.3 0 top
C1102  SCD1U16V2KX-3DLGP  [C402H22]  73.96 152.43 0 top
C1103  SCD1U16V2KX-L-GP  [C402H22]  137.92 172.21 180 top
C1104  SCD1U16V2KX-L-GP  [C402H22]  138.81 172.21 180 top
C1105  SCD1U16V2KX-3DLGP  [C402H22]  9.67 171.96 0 top
C1106  SCD1U16V2KX-3DLGP  [C402H22]  11.91 170.87 0 top
C1107  SC4D7U6D3V3KX-DLGP  [C603H36]  12.52 172.44 270 top
C1108  SCD1U16V2KX-L-GP  [C402H22]  77.72 170.43 90 top
C1109  SCD1U16V2KX-3DLGP  [C402H22]  121.24 172.92 135 top
C1110  SC2D2U6D3V2MX-DL-GP  [C402H22]  120.61 173.53 135 top
C1201  SCD1U16V2KX-3DLGP  [C402H22]  61.7 152.56 0 top
C1202  SCD1U16V2KX-3DLGP  [C402H22]  62.56 152.56 0 top
C1203  SC1U10V2KX-1DLGP  [C402H22]  85.98 152.23 0 top
C1204  SC4D7U6D3V3KX-DLGP  [C603H36]  81.92 170.81 90 top
C1205  SCD1U16V2KX-3DLGP  [C402H22]  81.92 171.83 90 top
C1206  SCD1U16V2KX-3DLGP  [C402H22]  136.02 172.21 180 top
C1207  SCD1U16V2KX-3DLGP  [C402H22]  136.91 172.21 180 top
C1208  SCD1U16V2KX-3DLGP  [C402H22]  18.01 170.99 0 top
C1209  SCD022U16V2KX-3DLGP  [C402H22]  15.04 174.65 90 top
C1210  SCD1U16V2KX-3DLGP  [C402H22]  15.24 170.43 90 top
C1211  SC4D7U6D3V3KX-DLGP  [C603H36]  15.49 171.53 90 top
C1212  SCD1U16V2KX-3DLGP  [C402H22]  121.88 172.29 135 top
C1213  SC2D2U6D3V2MX-DL-GP  [C402H22]  122.49 171.68 135 top
C1801  SC15P50V2JN-DL-GP  [C402H22]  146.23 105.69 270 top
C1802  SC15P50V2JN-DL-GP  [C402H22]  148.16 105.69 90 top
C1803  SC15P50V2JN-DL-GP  [C402H22]  170.26 144.04 90 top
C1804  SC15P50V2JN-DL-GP  [C402H22]  168.23 144.04 270 top
C2006  SC1U10V2KX-1DLGP  [C402H22]  167.54 150.93 90 top
C2007  SC1U10V2KX-1DLGP  [C402H22]  166.32 148.08 90 top
C2101  SCD1U16V2KX-3DLGP  [C402H22]  167.87 139.01 90 top
C2102  SCD1U16V2KX-3DLGP  [C402H22]  171.7 145.92 0 top
C2103  SC1U10V2KX-1DLGP  [C402H22]  171.7 147.96 180 top
C2104  SCD1U16V2KX-3DLGP  [C402H22]  157.58 149.41 180 top
C2105  SCD1U16V2KX-3DLGP  [C402H22]  156.69 149.41 180 top
C2106  SCD1U16V2KX-3DLGP  [C402H22]  157.1 144.53 270 top
C2107  SCD1U16V2KX-3DLGP  [C402H22]  170.13 138.56 180 top
C2108  SC4D7U6D3V3KX-DLGP  [C603H36]  166.93 115.42 0 top
C2109  SC4D7U6D3V3KX-DLGP  [C603H36]  167.8 113.46 90 top
C2110  SC1U10V2KX-1DLGP  [C402H22]  143.69 138.99 180 top
C2111  SC22U6D3V3MX-1-DL-GP  [C603H40]  146.1 139.37 180 top
C2112  SC22U6D3V3MX-1-DL-GP  [C603H40]  144.83 139.37 180 top
C2113  SCD1U16V2KX-3DLGP  [C402H22]  154.94 147.96 270 top
C2114  SCD1U16V2KX-3DLGP  [C402H22]  154.94 148.84 270 top
C2115  SCD1U16V2KX-3DLGP  [C402H22]  138.23 107.85 0 top
C2116  SCD1U16V2KX-3DLGP  [C402H22]  167.39 130.56 90 top
C2117  SCD1U16V2KX-3DLGP  [C402H22]  168.73 139.9 270 top
C2118  SC22U6D3V3MX-1-DL-GP  [C603H40]  143.79 103.81 90 top
C2119  SC22U6D3V3MX-1-DL-GP  [C603H40]  143.77 102.54 90 top
C2120  SC1U10V2KX-1DLGP  [C402H22]  154.05 142.62 0 top
C2121  SC1U10V2KX-1DLGP  [C402H22]  147.7 139.83 270 top
C2122  SC1U10V2KX-1DLGP  [C402H22]  184.61 147.6 0 top
C2123  SC1U10V2KX-1DLGP  [C402H22]  162.31 140.21 0 top
C2124  SC1U10V2KX-1DLGP  [C402H22]  155.07 144.78 180 top
C2125  SC1U10V2KX-1DLGP  [C402H22]  168.66 138.13 90 top
C2126  SC10U6D3V3MX-DL-GP  [C603H36]  170.14 128.02 90 top
C2127  SC22U6D3V3MX-1-DL-GP  [C603H40]  183.51 147.28 0 top
C2128  SC1U10V2KX-1DLGP  [C402H22]  147.69 142.6 270 top
C2129  SC22U6D3V3MX-1-DL-GP  [C603H40]  147.69 141.48 270 top
C2401  SC100P50V2JN-3DLGP  [C402H22]  104.32 43.54 90 top
C2402  SC2200P50V2KX-2DLGP  [C402H22]  180.85 19.81 180 top
C2403  SC100P50V2JN-3DLGP  [C402H22]  151.1 170.92 180 top
C2404  SC2200P50V2KX-2DLGP  [C402H22]  181.74 18.03 180 top
C2405  SC1U10V2KX-1DLGP  [C402H22]  171.2 10.9 0 top
C2406  SCD1U16V2KX-3DLGP  [C402H22]  163.7 11.13 0 top
C2407  SCD01U50V2KX-1DLGP  [C402H22]  184.53 21.34 90 top
C2408  SCD1U16V2KX-3DLGP  [C402H22]  175.69 12.01 90 top
C2411  SC4D7U6D3V3KX-DLGP  [C603H36]  180.01 9.73 90 top
C2412  SC1U10V2KX-1DLGP  [C402H22]  176.17 35.61 90 top
C2413  SC100P50V2JN-3DLGP  [C402H22]  183.44 29.46 90 top
C2414  SC4D7U6D3V3KX-DLGP  [C603H36]  161.59 9.86 0 top
C2415  SCD1U16V2KX-3DLGP  [C402H22]  180.47 11.79 90 top
C2416  SCD1U16V2KX-3DLGP  [C402H22]  172.09 10.9 0 top
C2417  SCD1U16V2KX-3DLGP  [C402H22]  160.25 26.64 180 top
C2418  SCD1U16V2KX-3DLGP  [C402H22]  182.55 21.16 90 top
C2419  SCD1U16V2KX-3DLGP  [C402H22]  182.91 27.94 180 top
C2420  SCD1U16V2KX-3DLGP  [C402H22]  176.63 34.09 180 top
C2421  SCD1U16V2KX-3DLGP  [C402H22]  175.74 34.09 180 top
C2422  SCD1U16V2KX-3DLGP  [C402H22]  171.7 33.78 270 top
C2423  SCD1U16V2KX-3DLGP  [C402H22]  171.73 32.89 270 top
C2424  SC10U6D3V3MX-DL-GP  [C603H36]  183.95 27.53 180 top
C2425  SCD1U16V2KX-3DLGP  [C402H22]  172.8 5.66 90 top
C2426  SCD01U50V2KX-1DLGP  [C402H22]  168.33 7.67 270 top
C2427  SC100P50V2JN-3DLGP  [C402H22]  132.59 39.24 270 top
C2501  SC1U10V2KX-1DLGP  [C402H22]  166.24 162.36 270 top
C2701  SC2D2U10V3KX-1DLGP-U  [C603H36]  61.34 266.83 0 top
C2702  SC2D2U10V3KX-1DLGP-U  [C603H36]  59.31 265.94 270 top
C2703  SC10U25V5KX-DL-GP  [C805H58]  70.74 267.54 180 top
C2704  SCD1U16V2KX-3DLGP  [C402H22]  72.26 265.56 180 top
C2705  SC10U25V5KX-DL-GP  [C805H58]  74.55 270 270 top
C2706  SC10U6D3V3MX-DL-GP  [C603H36]  58.82 263.24 0 top
C2707  SCD1U16V2KX-3DLGP  [C402H22]  60.12 262.66 0 top
C2708  SCD1U16V2KX-3DLGP  [C402H22]  73.15 265.56 180 top
C2709  SC10U25V5KX-DL-GP  [C805H58]  74.55 267.97 270 top
C2710  SC10U25V5KX-DL-GP  [C805H58]  73.79 262.61 90 top
C2711  SC10U25V5KX-DL-GP  [C805H58]  59.86 255.69 0 top
C2712  SCD1U16V2KX-3DLGP  [C402H22]  58.34 256.21 0 top
C2713  SC10U6D3V3MX-DL-GP  [C603H36]  66.59 247.62 0 top
C2714  SCD1U16V2KX-3DLGP  [C402H22]  58.83 253.44 270 top
C2715  SC22P50V2JN-4DLGP  [C402H22]  61.57 252.76 270 top
C2716  SCD1U16V2KX-3DLGP  [C402H22]  65.41 251.08 270 top
C2717  SCD1U16V2KX-3DLGP  [C402H22]  67.35 250.86 90 top
C2718  SCD1U16V2KX-3DLGP  [C402H22]  63.98 251 0 top
C2719  SCD1U50V3KX-DL-GP  [C603H35]  59.05 275.84 90 top
C2720  SCD1U50V3KX-DL-GP  [C603H35]  73.86 275.87 270 top
C2721  SCD1U16V2KX-3DLGP  [C402H22]  54.79 262.51 90 top
C2722  SC22U6D3V5MX-2DLGP  [C805H54]  50.22 262.81 0 top
C2901  SC10U25V5KX-DL-GP  [C805H58]  73.79 258.55 90 top
C2902  SC10U25V5KX-L-GP  [C805H56]  73.79 260.58 90 top
C2903  SC100P50V2JN-3DLGP  [C402H22]  70.87 271.65 90 top
C2904  SC4D7U25V5KX-DL-GP  [C805H54]  63.75 265.61 90 top
C2905  SC4D7U25V5KX-DL-GP  [C805H54]  67.34 266.5 270 top
C2906  SC100P50V2JN-3DLGP  [C402H22]  68.33 271.14 0 top
C2907  SC100P50V2JN-3DLGP  [C402H22]  63.5 271.02 0 top
C3001  SC10U25V5KX-DL-GP  [C805H58]  23.62 18.92 270 top
C3002  SC10U25V5KX-DL-GP  [C805H58]  19.94 18.92 90 top
C3003  SC100P50V2JN-3DLGP  [C402H22]  20.83 14.35 90 top
C3004  SC100P50V2JN-3DLGP  [C402H22]  22.73 14.35 270 top
C3005  SC100P50V2JN-3DLGP  [C402H22]  29.34 16.13 270 top
C3006  SC100P50V2JN-3DLGP  [C402H22]  26.42 16.13 90 top
C3007  SC10U25V5KX-DL-GP  [C805H58]  17.65 26.04 0 top
C3008  SC10U25V5KX-DL-GP  [C805H58]  19.68 23.62 0 top
C3009  SC100P50V2JN-3DLGP  [C402H22]  12.06 22.73 180 top
C3010  SC100P50V2JN-3DLGP  [C402H22]  12.06 24.64 0 top
C3101  SCD1U16V2KX-3DLGP  [C402H22]  133.22 29.31 180 top
C3102  SC4D7U6D3V3KX-DLGP  [C603H36]  132.16 29.67 180 top
C3103  SCD1U16V2KX-3DLGP  [C402H22]  143.13 29.16 90 top
C3104  SC4D7U6D3V3KX-DLGP  [C603H36]  143.05 28.04 90 top
C3105  SCD1U16V2KX-3DLGP  [C402H22]  143.46 26.85 90 top
C3106  SCD1U16V2KX-3DLGP  [C402H22]  136.59 28.49 270 top
C3107  SCD1U16V2KX-3DLGP  [C402H22]  132.54 25.53 270 top
C3108  SCD1U16V2KX-3DLGP  [C402H22]  132.59 22.05 270 top
C3109  SCD1U16V2KX-3DLGP  [C402H22]  143.31 21.72 90 top
C3110  SCD1U16V2KX-3DLGP  [C402H22]  143.31 20.83 90 top
C3111  SCD1U16V2KX-3DLGP  [C402H22]  143.46 24.69 90 top
C3112  SC1U10V2KX-1DLGP  [C402H22]  143.46 25.58 90 top
C3113  SCD1U16V2KX-3DLGP  [C402H22]  135.41 19.94 270 top
C3114  SC4D7U6D3V3KX-DLGP  [C603H36]  135.25 18.92 270 top
C3115  SCD1U16V2KX-3DLGP  [C402H22]  140.23 19.94 90 top
C3116  SCD1U16V2KX-3DLGP  [C402H22]  140.23 19.05 90 top
C3117  SC10U6D3V3MX-DL-GP  [C603H36]  135.25 17.65 270 top
C3118  SC20P50V2JN-1-DL-GP  [C402H22]  136.32 29.44 90 top
C3119  SC20P50V2JN-1-DL-GP  [C402H22]  138.48 29.46 90 top
C3201  SC1U10V2KX-1DLGP  [C402H22]  124.18 17.42 0 top
C3301  SCD1U16V2KX-3DLGP  [C402H22]  38.23 254.25 270 top
C3302  SC4D7U6D3V3KX-DLGP  [C603H36]  37.85 253.24 270 top
C3303  SC1U10V2KX-1DLGP  [C402H22]  33.48 257.61 270 top
C3304  SC1U10V2KX-1DLGP  [C402H22]  42.95 255.22 0 top
C3305  SC6D8P50V2CN-DL-GP  [C402H22]  42.21 262.23 0 top
C3306  SC10U6D3V3MX-DL-GP  [C603H36]  41.15 264.8 270 top
C3307  SCD1U16V2KX-3DLGP  [C402H22]  41.15 265.94 270 top
C3801  SCD1U16V2KX-3DLGP  [C402H22]  83.33 256.75 135 top
C3802  SCD1U16V2KX-3DLGP  [C402H22]  82.7 257.38 135 top
C3803  SCD1U16V2KX-3DLGP  [C402H22]  100.85 258.87 135 top
C3804  SCD1U16V2KX-3DLGP  [C402H22]  100.22 259.5 135 top
C3805  SC1U10V2KX-1DLGP  [C402H22]  87.38 257.3 270 top
C3806  SCD1U16V2KX-3DLGP  [C402H22]  77.44 258.06 270 top
C3807  SCD1U16V2KX-3DLGP  [C402H22]  80.14 265.05 90 top
C3901  SC1U10V2KX-1DLGP  [C402H22]  82.75 27.71 270 top
C4007  SCD1U16V2KX-3DLGP  [C402H22]  112.01 31.5 270 top
C4008  SCD1U16V2KX-3DLGP  [C402H22]  109.86 32.59 0 top
C4009  SC1U10V2KX-1DLGP  [C402H22]  103.1 171.27 180 top
C4010  SCD1U16V2KX-3DLGP  [C402H22]  93.98 171.83 270 top
C4011  SCD1U16V2KX-3DLGP  [C402H22]  26.59 175.54 90 top
C4012  SC1U10V2KX-1DLGP  [C402H22]  29.46 172.97 270 top
C4013  SC1U10V2KX-1DLGP  [C402H22]  24.26 172.34 180 top
C4201  SC1KP50V2KX-1DLGP  [C402H22]  8 216.81 90 top
C4202  SC1KP50V2KX-1DLGP  [C402H22]  8 215.9 90 top
C4203  SC1U10V2KX-1DLGP  [C402H22]  7.41 222.87 180 top
C4204  SC1U10V2KX-1DLGP  [C402H22]  5.31 222.55 180 top
C4205  SC10U6D3V3MX-DL-GP  [C603H36]  8.76 212.46 90 top
C4206  SC10U6D3V3MX-DL-GP  [C603H36]  8.76 213.68 90 top
C4207  SC10U25V5KX-L-GP  [C805H56]  6.58 209.83 0 top
C4208  SC10U25V5KX-DL-GP  [C805H58]  8.55 209.85 0 top
C4209  SCD1U25V2KX-1-DL-GP  [C402H22]  36.73 192.13 270 top
C4210  SCD1U25V2KX-1-DL-GP  [C402H22]  38.18 191.59 0 top
C4211  SC10U25V5KX-L-GP  [C805H56]  37.08 188.09 0 top
C4212  SCD1U16V2KX-3DLGP  [C402H22]  38.61 188.21 0 top
C4218  SCD1U16V2KX-3DLGP  [C402H22]  184.48 189.87 90 top
C4219  SCD01U50V2KX-L-GP  [C402H22]  186.69 193.68 180 top
C4220  SCD1U16V2KX-3DLGP  [C402H22]  18.06 41.62 180 top
C4221  SC2D2U25V3KX-1-GP  [C603H40]  16.92 41.62 180 top
C4222  SCD1U16V2KX-3DLGP  [C402H22]  23.56 41.27 90 top
C4223  SC2D2U25V3KX-1-GP  [C603H40]  23.43 42.37 90 top
C4224  SC1U10V2KX-1DLGP  [C402H22]  19.91 41.62 180 top
C4225  SCD1U16V2KX-3DLGP  [C402H22]  19 41.62 180 top
C4226  SC1U10V2KX-1DLGP  [C402H22]  188.15 192.18 270 top
C4227  SC1U10V2KX-1DLGP  [C402H22]  25.34 36.12 270 top
C4301  SCD1U16V2KX-3DLGP  [C402H22]  165.61 189.48 180 top
C4302  SCD1U16V2KX-3DLGP  [C402H22]  167.13 189.99 270 top
C4303  SC1U50V3KX-1-GP  [C603H36]  6.22 130.94 270 top
C4304  SC1U50V3KX-1-GP  [C603H36]  173.43 188.77 270 top
C5101  SCD1U16V2KX-3DLGP  [C402H22]  195.12 190.27 90 top
C5601  SCD1U16V2KX-3DLGP  [C402H22]  81.28 25.07 0 top
C5602  SCD1U16V2KX-3DLGP  [C402H22]  80.39 25.07 0 top
C5603  SCD1U16V2KX-3DLGP  [C402H22]  77.22 25.2 0 top
C5604  SCD1U16V2KX-3DLGP  [C402H22]  76.33 25.2 0 top
C5605  SCD1U16V2KX-3DLGP  [C402H22]  74.3 22.89 0 top
C5606  SCD1U16V2KX-3DLGP  [C402H22]  73.41 22.89 0 top
C5607  SCD1U16V2KX-3DLGP  [C402H22]  72.39 25.7 0 top
C5608  SCD1U16V2KX-3DLGP  [C402H22]  71.37 25.7 0 top
C5609  SCD1U25V2KX-1-DL-GP  [C402H22]  68.45 26.29 90 top
C5610  SC470P50V2KX-3DLGP  [C402H22]  69.09 17.78 90 top
C5611  SC470P50V2KX-3DLGP  [C402H22]  67.18 17.78 270 top
C5901  SC2D2U10V3KX-1DLGP-U  [C603H36]  53.19 14.3 0 top
C5902  SCD1U16V2KX-3DLGP  [C402H22]  52.17 14.68 0 top
C5903  SCD1U16V2KX-3DLGP  [C402H22]  62.31 19.96 270 top
C5904  SCD1U16V2KX-3DLGP  [C402H22]  54.36 24.56 270 top
C5905  SCD1U16V2KX-3DLGP  [C402H22]  54.74 14.22 90 top
C5906  SCD1U16V2KX-3DLGP  [C402H22]  52.37 23.39 270 top
C5907  SC4D7U6D3V3KX-DLGP  [C603H36]  52.04 24.43 270 top
C5908  SCD1U16V2KX-3DLGP  [C402H22]  62.18 16 90 top
C5909  SCD1U16V2KX-3DLGP  [C402H22]  50.95 22.86 180 top
C5910  SCD1U16V2KX-3DLGP  [C402H22]  62.18 18.16 90 top
C5911  SCD1U16V2KX-3DLGP  [C402H22]  62.18 19.05 90 top
C5912  SCD1U16V2KX-3DLGP  [C402H22]  62.31 20.83 90 top
C5913  SCD1U16V2KX-3DLGP  [C402H22]  62.31 21.72 90 top
C5914  SCD1U16V2KX-3DLGP  [C402H22]  61.34 22.94 90 top
C5915  SCD1U16V2KX-3DLGP  [C402H22]  61.34 24 90 top
C5916  SC22P50V2JN-4DLGP  [C402H22]  44.02 14.61 270 top
C5917  SC22P50V2JN-4DLGP  [C402H22]  46.18 14.61 270 top
C5918  SC22P50V2JN-4DLGP  [C402H22]  48.34 14.61 270 top
C5919  SC22P50V2JN-4DLGP  [C402H22]  44.2 11.05 270 top
C5920  SC22P50V2JN-4DLGP  [C402H22]  46.23 11.05 270 top
C5921  SC22P50V2JN-4DLGP  [C402H22]  48.51 11.05 270 top
C5922  SC2P50V2CN-3-GP  [C402H22]  40.26 18.49 0 top
C5923  SC2P50V2CN-3-GP  [C402H22]  39.4 17.48 180 top
C6001  SCD01U50V2KX-1DLGP  [C402H22]  110.1 193.78 180 top
C6002  SCD01U50V2KX-1DLGP  [C402H22]  109.08 193.78 180 top
C6003  SCD01U50V2KX-1DLGP  [C402H22]  113.91 193.65 180 top
C6004  SCD01U50V2KX-1DLGP  [C402H22]  112.89 193.65 180 top
C6005  SCD01U50V2KX-1DLGP  [C402H22]  166.14 179.6 90 top
C6006  SCD01U50V2KX-1DLGP  [C402H22]  166.14 180.62 90 top
C6007  SCD01U50V2KX-1DLGP  [C402H22]  166.14 181.64 90 top
C6008  SCD01U50V2KX-1DLGP  [C402H22]  166.14 182.65 90 top
C6009  SCD01U50V2KX-1DLGP  [C402H22]  129.15 194.06 180 top
C6010  SCD01U50V2KX-1DLGP  [C402H22]  130.03 194.06 180 top
C6011  SCD01U50V2KX-1DLGP  [C402H22]  133.84 194.06 180 top
C6012  SCD01U50V2KX-1DLGP  [C402H22]  132.96 194.06 180 top
C6013  SC10U25V5KX-DL-GP  [C805H58]  92.08 193.68 270 top
C6014  SC10U25V5KX-DL-GP  [C805H58]  103.38 195.2 90 top
C6201  SC1U10V2KX-1DLGP  [C402H22]  131.83 18.03 180 top
C6203  SCD1U16V2KX-3DLGP  [C402H22]  145.19 18.06 180 top
C6205  SCD1U16V2KX-3DLGP  [C402H22]  146.1 18.08 180 top
C6206  SC10U25V5KX-DL-GP  [C805H58]  147.55 18.95 180 top
C6209  SCD22U10V2KX-2-GP  [C402H22]  141.99 5.51 270 top
C6210  SCD22U10V2KX-2-GP  [C402H22]  141.99 4.62 270 top
C6211  SCD22U10V2KX-2-GP  [C402H22]  147.24 5.33 270 top
C6212  SCD22U10V2KX-2-GP  [C402H22]  147.24 4.45 270 top
C6213  SCD1U16V2KX-3DLGP  [C402H22]  130.81 18.03 180 top
C6214  SC10U25V5KX-DL-GP  [C805H58]  149.5 18.95 180 top
C6215  SCD1U16V2KX-3DLGP  [C402H22]  169.86 105.94 45 top
C6301  SCD1U16V2KX-3DLGP  [C402H22]  43.33 231.72 180 top
C6302  SCD1U16V2KX-3DLGP  [C402H22]  44.22 231.72 180 top
C6303  SCD1U16V2KX-3DLGP  [C402H22]  44.81 208.79 0 top
C6304  SCD1U16V2KX-3DLGP  [C402H22]  45.82 208.79 0 top
C6305  SCD1U16V2KX-3DLGP  [C402H22]  32.41 215.06 0 top
C6306  SCD1U16V2KX-3DLGP  [C402H22]  31.52 215.06 0 top
C6307  SC10U6D3V3MX-DL-GP  [C603H36]  42.29 231.9 180 top
C6308  SC22U6D3V3MX-1-DL-GP  [C603H40]  40.84 232.96 180 top
C6309  SCD1U16V2KX-3DLGP  [C402H22]  46.84 208.79 0 top
C6310  SCD1U16V2KX-3DLGP  [C402H22]  40.01 234.95 90 top
C6402  SCD1U16V2KX-3DLGP  [C402H22]  11.96 233.48 180 top
C6403  SCD1U16V2KX-3DLGP  [C402H22]  11.96 231.32 0 top
C6404  SC1U10V2KX-1DLGP  [C402H22]  18.64 240 270 top
C9101  SC10U6D3V3MX-DL-GP  [C603H36]  157.99 170.56 270 top
C9102  SCD1U16V2KX-3DLGP  [C402H22]  167.06 174.75 180 top
C9103  SCD1U16V2KX-3DLGP  [C402H22]  160.32 168.55 0 top
C9104  SC10U6D3V3MX-DL-GP  [C603H36]  157.56 176.35 0 top
C9105  SCD1U16V2KX-3DLGP  [C402H22]  158.62 176.33 0 top
C9106  SCD1U16V2KX-3DLGP  [C402H22]  163.55 163.19 270 top
C9301  SCD22U10V2KX-2-GP  [C402H22]  177.16 61.85 90 top
C9302  SCD22U10V2KX-2-GP  [C402H22]  177.16 65.05 90 top
C9303  SCD22U10V2KX-2-GP  [C402H22]  177.16 68.99 90 top
C9304  SCD22U10V2KX-2-GP  [C402H22]  177.16 60.99 90 top
C9305  SCD22U10V2KX-2-GP  [C402H22]  177.16 65.91 90 top
C9306  SCD22U10V2KX-2-GP  [C402H22]  177.16 69.85 90 top
C9307  SCD22U10V2KX-2-GP  [C402H22]  177.16 73.91 90 top
C9308  SCD22U10V2KX-2-GP  [C402H22]  177.16 73.05 90 top
C9309  SCD22U10V2KX-2-GP  [C402H22]  177.16 79.88 90 top
C9310  SCD1U16V2KX-3DLGP  [C402H22]  177.29 46.99 180 top
C9311  SCD1U16V2KX-3DLGP  [C402H22]  174.37 55.63 180 top
C9312  SCD1U16V2KX-3DLGP  [C402H22]  168.55 54.76 0 top
C9313  SCD22U10V2KX-2-GP  [C402H22]  177.16 79.02 90 top
C9314  SCD22U10V2KX-2-GP  [C402H22]  177.16 83.95 90 top
C9315  SCD22U10V2KX-2-GP  [C402H22]  177.16 83.08 90 top
C9316  SCD22U10V2KX-2-GP  [C402H22]  177.16 87.88 90 top
C9317  SCD22U10V2KX-2-GP  [C402H22]  177.16 87.02 90 top
C9318  SCD22U10V2KX-2-GP  [C402H22]  177.29 91.95 90 top
C9319  SCD22U10V2KX-2-GP  [C402H22]  177.29 91.08 90 top
C9320  SCD22U10V2KX-2-GP  [C402H22]  177.16 95.89 90 top
C9321  SCD22U10V2KX-2-GP  [C402H22]  177.16 95.02 90 top
C9322  SCD22U10V2KX-2-GP  [C402H22]  177.16 101.17 90 top
C9323  SCD22U10V2KX-2-GP  [C402H22]  177.16 100.3 90 top
C9324  SCD22U10V2KX-2-GP  [C402H22]  177.04 105.28 90 top
C9325  SCD22U10V2KX-2-GP  [C402H22]  177.04 104.42 90 top
C9326  SCD22U10V2KX-2-GP  [C402H22]  177.04 109.35 90 top
C9328  SCD22U10V2KX-2-GP  [C402H22]  177.04 108.48 90 top
C9329  SCD22U10V2KX-2-GP  [C402H22]  176.91 113.41 90 top
C9331  SCD22U10V2KX-2-GP  [C402H22]  176.91 112.52 90 top
C9332  SCD22U10V2KX-2-GP  [C402H22]  176.91 116.59 90 top
C9334  SCD22U10V2KX-2-GP  [C402H22]  176.91 115.72 90 top
C9335  SCD22U10V2KX-2-GP  [C402H22]  177.16 119 90 top
C9336  SCD22U10V2KX-2-GP  [C402H22]  177.16 119.89 90 top
C9337  SCD22U10V2KX-2-GP  [C402H22]  177.42 122.94 90 top
C9338  SCD22U10V2KX-2-GP  [C402H22]  177.42 123.83 90 top
C9401  SCD22U10V2KX-2-GP  [C402H22]  157.1 56.9 90 top
C9402  SCD22U10V2KX-2-GP  [C402H22]  157.1 57.78 90 top
C9403  SCD1U16V2KX-3DLGP  [C402H22]  169.06 50.34 0 top
C9404  SCD1U16V2KX-3DLGP  [C402H22]  175.13 52.83 270 top
C9405  SCD1U16V2KX-3DLGP  [C402H22]  169.04 46.99 180 top
C9410  SCD1U16V2KX-3DLGP  [C402H22]  175.13 51.94 270 top
C9411  SC10U6D3V3MX-DL-GP  [C603H36]  177.04 50.16 0 top
C9901  SCD1U16V2KX-3DLGP  [C402H22]  181 168.22 90 top
C9902  SCD1U16V2KX-3DLGP  [C402H22]  16.62 237.08 90 top
C9903  SCD1U16V2KX-3DLGP  [C402H22]  21.42 237.06 90 top
C9904  SCD1U16V2KX-3DLGP  [C402H22]  19.47 237.08 90 top
C9905  SCD1U16V2KX-3DLGP  [C402H22]  23.35 237.06 90 top
C9907  SCD1U16V2KX-3DLGP  [C402H22]  58.26 228.53 135 top
C9908  SCD1U16V2KX-3DLGP  [C402H22]  57.28 229.54 135 top
C9909  SCD1U16V2KX-3DLGP  [C402H22]  60.3 221.7 0 top
C9910  SCD1U16V2KX-3DLGP  [C402H22]  54.33 227.42 0 top
C9911  SCD1U16V2KX-3DLGP  [C402H22]  56.08 225.77 315 top
CPU1  SKYLAKE-1,SKL-S,LAKE-S  [SKTBGA1151R754612-UH369]  75.11 98 180 top
D2501  RB551V30-GP  [SOD323AKH38]  49.12 258.47 270 top
D2502  BAT54C-12-GP  [SOT-23-9H44]  53.24 259.99 270 top
D2601  RB551V30-GP  [SOD323AKH38]  12.45 135.51 90 top
D2602  RB551V30-GP  [SOD323AKH38]  106.17 259.46 90 top
D2701  AZ5125-01H-R7G-GP  [SOD-523-4H28]  75.92 271.91 90 top
D2901  LBAT54ALT1G-1-GP  [SOT23-2D4-123H44]  65.9 270.59 180 top
D4301  P4SSMJ24AGP-GP  [D5126145AKH91]  11.3 130.56 270 top
D4302  P4SSMJ24AGP-GP  [D5126145AKH91]  174.24 186.31 90 top
D5601  RB551V30-GP  [SOD323AKH38]  65.41 27.94 90 top
D6301  RB551V30-GP  [SOD323AKH38]  36.27 240.23 0 top
D6302  RB551V30-GP  [SOD323AKH38]  33.88 240.23 0 top
DB2001  0R3J-0-U-GP  [R603H22]  171.22 138.79 0 top
DB2002  0R3J-0-U-GP  [R603H22]  154.74 27.41 180 top
DIMM1  DDR4-288P-82-GP  [AH08847-A9L2-4M]  81.6 158.5 0 top
DIMM2  DDR4-288P-82-GP  [AH08847-A9L2-4M]  81.6 166.1 0 top
EU3201  AZC199-04SDR7G-1-GP  [SOT-6-1H58]  123.32 25.4 270 top
EU3202  AZC199-04SDR7G-1-GP  [SOT-6-1H58]  109.09 28.96 270 top
EU3203  AZC199-04SDR7G-1-GP  [SOT-6-1H58]  123.32 21.21 270 top
EU3204  AZC199-04SDR7G-1-GP  [SOT-6-1H58]  123.37 29.51 270 top
EU3801  AZ1045-04F-R7G-GP  [DFN10G2510H26]  82.93 265.18 180 top
EU3802  AZ1045-04F-R7G-GP  [DFN10G2510H26]  103.86 264.59 135 top
EU3803  AZC199-04SDR7G-1-GP  [SOT-6-1H58]  98.44 264.57 315 top
EU3901  AZC199-04SDR7G-1-GP  [SOT-6-1H58]  93.75 19.86 180 top
EU5601  AZ1045-04F-R7G-GP  [DFN10G2510H26]  77.47 16.38 0 top
EU5602  AZ1045-04F-R7G-GP  [DFN10G2510H26]  73.15 16.46 0 top
EU5603  AZ1045-04F-R7G-GP  [DFN10G2510H26]  68.07 15.47 0 top
EU5901  TVLST2304BD0-1-GP  [SOT-6H58]  39.55 12.52 90 top
EU5902  TVLST2304BD0-1-GP  [SOT-6H58]  32.69 12.45 180 top
F3301  POLYSW-1D5A6V-12-GP  [POLYSW-2114H30]  40.39 254.25 0 top
F5901  POLYSW-1D1A6V-9-GP-U  [POLYSW-2114H30]  45.94 23.01 270 top
FANC1  BAOT-CON4-S5-GP  [P254-1104A0ADKP-W]  7 138.7 90 top
FANS1  FOX-CON4-S19-GP  [HF2704F-RM1]  100.5 254 0 top
FL2901  MCB1005S121FBP-GP  [L402H24]  70.87 270.64 270 top
FL2902  MCB1005S121FBP-GP  [L402H24]  62.48 271.02 180 top
FL2903  MCB1005S121FBP-GP  [L402H24]  69.34 271.14 180 top
HDMI1  SKT-HDMI23-47-GP-U  [SKT-HDMI23-150122-9-U]  67 9.25 0 top
HPMIC1  AUDIO-JK521-GP  [C35012W-L101-39AA00R]  66.72 283.69 0 top
HS1901  FOX-CON2-3-GP  [HB9603E-DW]  134 146.4 270 top
HS1902  FOX-CON2-3-GP  [HB9603E-DW]  170.6 100.6 90 top
HS2601  GEN330R190-8-F-C-GP  [GEN330R190-8-F-C]  6.35 33.02 0 top
HS2602  GEN315R158-8-F-C-S-GP-U  [GEN315R158-8-F-C-S-U]  6.35 184.6 180 top
HS2603  GEN315R158-8-F-C-S-GP-U  [GEN315R158-8-F-C-S-U]  17.35 254 180 top
HS2604  GEN330R190-8-F-C-GP  [GEN330R190-8-F-C]  115.45 254.2 0 top
HS2605  GEN315R158-8-F-C-S-GP-U  [GEN315R158-8-F-C-S-U]  193.65 197.65 180 top
HS2606  GEN315R158-8-F-C-S-GP-U  [GEN315R158-8-F-C-S-U]  193.65 29.85 180 top
HS6301  STF256R109H99-GP  [STF256R109H99]  67.98 218.92 180 top
JMP1  PIN-CONN6A-S3-GP  [21S-92-03GB16]  194.94 14.86 270 top
L2101  HCB1608KF-601T10-GP  [L603H38]  148.11 138.63 270 top
L2102  HCB1608KF-601T10-GP  [L603H38]  144.3 100.56 225 top
L2701  MHC1608S800QBP-GP  [L603H38]  73.91 274.57 90 top
L2702  MHC1608S800QBP-GP  [L603H38]  65.28 247.65 180 top
L2703  MHC1608S800QBP-GP  [L603H38]  67.79 247.62 180 top
L3001  MCB1005S121FBP-GP  [L402H24]  23.62 15.37 90 top
L3002  MCB1005S121FBP-GP  [L402H24]  20.83 15.37 270 top
L3003  MCB1005S121FBP-GP  [L402H24]  26.42 17.14 270 top
L3004  MCB1005S121FBP-GP  [L402H24]  29.34 17.14 90 top
L3005  MCB1005S121FBP-GP  [L402H24]  13.46 24.84 270 top
L3006  MCB1005S121FBP-GP  [L402H24]  13.46 22.35 270 top
L5901  MHC1608S600QBP-GP  [L603H38]  62.48 17.07 270 top
L5902  MHC1608S600QBP-GP  [L603H38]  49.15 22.4 90 top
L5903  BLM18BB470SN1D-GP  [L1608-UH38]  48.77 12.83 0 top
L5904  BLM18BB470SN1D-GP  [L1608-UH38]  46.61 12.83 0 top
L5905  BLM18BB470SN1D-GP  [L1608-UH38]  44.58 12.83 0 top
LED1  LED-W-45-GP  [LED1608AKH28]  19.07 278.1 270 top
LPC1  ACES-CON14-5-GP  [87212-1400N]  190.47 10.46 270 top
NGFF1  SKT-NGFF75P-91-GP  [AS0BC21-S40BE-7H]  39.73 218.92 90 top
NGFF2  SKT-NGFF75P-90-GP-U  [AS0BC21-S85BM-7H]  140 14 180 top
NOREF  -  []  27.06 136.84 0 top
NOREF#2  -  []  29.57 124.08 0 top
NOREF#3  -  []  145.58 183.24 0 top
NOREF#4  *  [unnamed#2]  22.61 23.24 0 top
NOREF#5  -  [unnamed#2]  140 95.6 270 top
NOREF#6  *  [unnamed#2]  174.12 97.16 0 top
NOREF#7  -  [unnamed#2]  5 23.76 0 top
NOREF#8  -  [unnamed#2]  194.7 241.75 0 top
NOREF#9  *  [unnamed#2]  189.74 44.7 0 top
NOREF#10  *  [unnamed#2]  143.76 85.09 0 top
NOREF#11  *  [unnamed#2]  34.16 69.72 0 top
NOREF#12  -  [unnamed#2]  5 239 0 top
NOREF#13  *  [unnamed#2]  133.86 46.99 0 top
NOREF#14  -  [unnamed#2]  195.25 214.51 0 top
NOREF#15  -  [unnamed#2]  140 87.6 270 top
NOREF#16  -  []  185.62 1.91 0 top
NOREF#17  *  [unnamed#2]  155.07 5.08 0 top
NOREF#18  -  []  -40.53 29.59 0 top
NOREF#19  *  [unnamed#2]  15.49 183.64 0 top
NOREF#20  -  [unnamed#2]  38.4 135.5 0 top
NOREF#21  -  [unnamed#2]  5.3 252.95 0 top
NOREF#22  -  []  0 0 0 top
NOREF#23  -  [unnamed#2]  140 45.6 270 top
NOREF#24  -  [unnamed#2]  140 37.6 270 top
NOREF#25  *  [unnamed#2]  188.47 141.1 0 top
NOREF#26  *  [unnamed#2]  16.58 47.41 0 top
NOREF#27  -  []  0 0 0 top
NOREF#28  *  [unnamed#2]  20.83 268.99 0 top
NOREF#29  *  [unnamed#2]  174.98 45.19 0 top
NOREF#30  -  [unnamed#2]  113.4 60.5 0 top
NOREF#31  -  [unnamed#2]  38.4 60.5 0 top
NOREF#32  -  []  0 0 0 top
NOREF#33  -  [unnamed#2]  113.4 135.5 0 top
NOREF#34  -  []  200 -40.49 90 top
NOREF#35  *  [unnamed#2]  16.76 143.51 0 top
NOREF#36  -  [unnamed#2]  195 5 0 top
NOREF#37  *  [unnamed#2]  184.4 186.56 0 top
NOREF#38  -  []  0 0 0 top
NOREF#39  -  []  48.69 146.51 0 top
NOREF#40  -  []  14.38 492.79 180 top
NOREF#41  -  [unnamed#2]  4.75 280.19 0 top
NOREF#42  *  [unnamed#2]  21.21 26.67 180 bottom
NOREF#43  *  [unnamed#2]  176.3 14.88 180 bottom
NOREF#44  *  [unnamed#3]  148.65 19.87 180 bottom
NOREF#45  *  [unnamed#3]  148.65 197.65 180 bottom
NOREF#46  -  []  466.59 2.4 180 bottom
PC1001  SC22U6D3V3MX-1-DL-GP  [C603H40]  79.68 100.2 90 top
PC1002  SC22U6D3V3MX-1-DL-GP  [C603H40]  79.04 102.17 0 top
PC1004  SC22U6D3V5MX-L3-GP  [C805H58]  73.05 97.82 180 top
PC1005  SC22U6D3V5MX-L3-GP  [C805H58]  79.65 94.14 180 top
PC1006  SC22U6D3V5MX-L3-GP  [C805H58]  77.37 94.14 0 top
PC1007  SC22U6D3V5MX-2DLGP  [C805H54]  75.21 94.26 180 top
PC1008  SC22U6D3V5MX-2DLGP  [C805H54]  73.05 94.14 0 top
PC1009  SC22U6D3V5MX-2DLGP  [C805H54]  62.99 68.96 270 top
PC1010  SC22U6D3V5MX-2DLGP  [C805H54]  71.37 68.96 270 top
PC1011  SC22U6D3V5MX-2DLGP  [C805H54]  79.38 68.96 270 top
PC1012  SC22U6D3V5MX-2DLGP  [C805H54]  70.89 94.16 180 top
PC1018  SC22U6D3V5MX-2DLGP  [C805H54]  79.63 97.82 0 top
PC1019  SC22U6D3V5MX-L3-GP  [C805H58]  77.37 97.69 180 top
PC1020  SC22U6D3V5MX-L3-GP  [C805H58]  77.37 101.37 0 top
PC1021  SC22U6D3V5MX-L3-GP  [C805H58]  75.21 97.87 0 top
PC1022  SC22U6D3V5MX-L3-GP  [C805H58]  75.21 101.57 180 top
PC1023  SC22U6D3V5MX-L3-GP  [C805H58]  73.03 101.4 0 top
PC1034  SC22U6D3V5MX-2DLGP  [C805H54]  35.51 73.18 0 top
PC1035  SC22U6D3V5MX-2DLGP  [C805H54]  30.12 106.53 180 top
PC1036  SC22U6D3V5MX-2DLGP  [C805H54]  32.16 106.53 180 top
PC1037  SC22U6D3V5MX-2DLGP  [C805H54]  35.43 81.03 0 top
PC1038  SC22U6D3V5MX-2DLGP  [C805H54]  35.37 88.8 0 top
PC1039  SC22U6D3V5MX-2DLGP  [C805H54]  35.51 96.6 0 top
PC1040  SC22U6D3V5MX-2DLGP  [C805H54]  68.73 94.18 180 top
PC1041  SC22U6D3V5MX-2DLGP  [C805H54]  66.6 94.21 180 top
PC1042  SC22U6D3V5MX-2DLGP  [C805H54]  70.92 97.82 180 top
PC1043  SC22U6D3V5MX-2DLGP  [C805H54]  68.73 97.82 180 top
PC1044  SC22U6D3V5MX-2DLGP  [C805H54]  66.6 97.82 180 top
PC1045  SC22U6D3V5MX-2DLGP  [C805H54]  67.44 102.62 90 top
PC1046  SC22U6D3V3MX-1-DL-GP  [C603H40]  69.84 101.21 0 top
PC1047  SC22U6D3V3MX-1-DL-GP  [C603H40]  71.32 101.21 0 top
PC1048  SC22U6D3V3MX-1-DL-GP  [C603H40]  83.24 94.95 270 top
PC1049  SC22U6D3V3MX-1-DL-GP  [C603H40]  80.31 102.16 0 top
PC1050  SC47U6D3V5MX-1DL-GP  [C805H54]  82.8 96.52 270 top
PC1051  SC47U6D3V5MX-1DL-GP  [C805H54]  82.8 98.55 270 top
PC1052  SC47U6D3V5MX-1DL-GP  [C805H54]  82.8 100.58 270 top
PC1053  SC47U6D3V5MX-1DL-GP  [C805H54]  82.8 102.62 270 top
PC1058  SC22U6D3V5MX-2DLGP  [C805H54]  67.44 100.58 90 top
PC4401  SC1U50V3KX-1-GP  [C603H36]  23.44 68.33 0 top
PC4402  SC2D2U10V3KX-1DLGP-U  [C603H36]  17.75 68.25 270 top
PC4403  SCD01U50V2KX-1DLGP  [C402H22]  17.2 69.35 90 top
PC4404  SC470P50V2KX-3DLGP  [C402H22]  27.38 61.72 270 top
PC4405  SC2200P50V2KX-2DLGP  [C402H22]  27.41 59.82 270 top
PC4406  SC33P50V2JN-3DLGP  [C402H22]  25.88 60.33 0 top
PC4407  SCD1U25V2KX-1-DL-GP  [C402H22]  24.13 47.88 0 top
PC4408  SCD1U25V2KX-1-DL-GP  [C402H22]  24.13 51.74 0 top
PC4409  SC1KP50V2KX-1DLGP  [C402H22]  24.99 64.68 90 top
PC4410  SCD1U25V2KX-1-DL-GP  [C402H22]  26.21 52.93 0 top
PC4411  SC3300P50V2KX-1DLGP  [C402H22]  24.99 65.56 270 top
PC4412  SCD1U25V2KX-1-DL-GP  [C402H22]  26.21 54.86 0 top
PC4413  SC220P50V2KX-3DLGP  [C402H22]  26.39 58.4 0 top
PC4414  SC470P50V2KX-3DLGP  [C402H22]  22.89 65.59 180 top
PC4415  SC1500P50V2KX-2-DL-GP  [C402H22]  25.5 58.4 0 top
PC4416  SC1KP50V2KX-1DLGP  [C402H22]  25.68 56.29 90 top
PC4417  SC470P50V2KX-3DLGP  [C402H22]  9.55 63.86 0 top
PC4418  SC2200P50V2KX-2DLGP  [C402H22]  10.82 60.68 0 top
PC4419  SC33P50V2JN-3DLGP  [C402H22]  11.84 60.68 0 top
PC4420  SCD1U25V2KX-1-DL-GP  [C402H22]  12.83 54.13 0 top
PC4421  SCD1U25V2KX-1-DL-GP  [C402H22]  12.9 52.22 0 top
PC4422  SC1KP50V2KX-1DLGP  [C402H22]  12.4 64.98 270 top
PC4423  SC3300P50V2KX-1DLGP  [C402H22]  12.32 65.89 90 top
PC4424  SC330P50V2KX-3-DL-GP  [C402H22]  11.28 58.72 0 top
PC4425  SC1500P50V2KX-2-DL-GP  [C402H22]  9.86 59.72 0 top
PC4426  SC470P50V2KX-3DLGP  [C402H22]  14.27 65.94 270 top
PC4427  SC1KP50V2KX-1DLGP  [C402H22]  11.96 57.1 270 top
PC4428  SCD1U25V2KX-1-DL-GP  [C402H22]  13.92 50.42 0 top
PC4429  SCD1U25V2KX-1-DL-GP  [C402H22]  21.16 49.48 0 top
PC4501  SC10U25V5KX-DL-GP  [C805H58]  48.79 33.12 180 top
PC4502  SC10U25V5KX-DL-GP  [C805H58]  50.83 33.12 180 top
PC4503  SCD1U50V3KX-DL-GP  [C603H35]  37.11 36.75 90 top
PC4504  SC1U50V3KX-1-GP  [C603H36]  34.24 31.6 270 top
PC4505  SC1500P50V2KX-2-DL-GP  [C402H22]  32.64 53.09 90 top
PC4506  SC10U25V5KX-DL-GP  [C805H58]  67.94 38.99 90 top
PC4507  SC10U25V5KX-DL-GP  [C805H58]  57.18 36.55 270 top
PC4508  SCD1U50V3KX-DL-GP  [C603H35]  55.14 40.87 90 top
PC4509  SC1U50V3KX-1-GP  [C603H36]  52.07 35.79 270 top
PC4510  SC1500P50V2KX-2-DL-GP  [C402H22]  50.01 55.68 270 top
PC4511  SC10U25V5KX-DL-GP  [C805H58]  74.45 39.19 180 top
PC4512  SC10U25V5KX-DL-GP  [C805H58]  76.48 39.19 180 top
PC4513  SCD1U50V3KX-DL-GP  [C603H35]  73.91 45.82 90 top
